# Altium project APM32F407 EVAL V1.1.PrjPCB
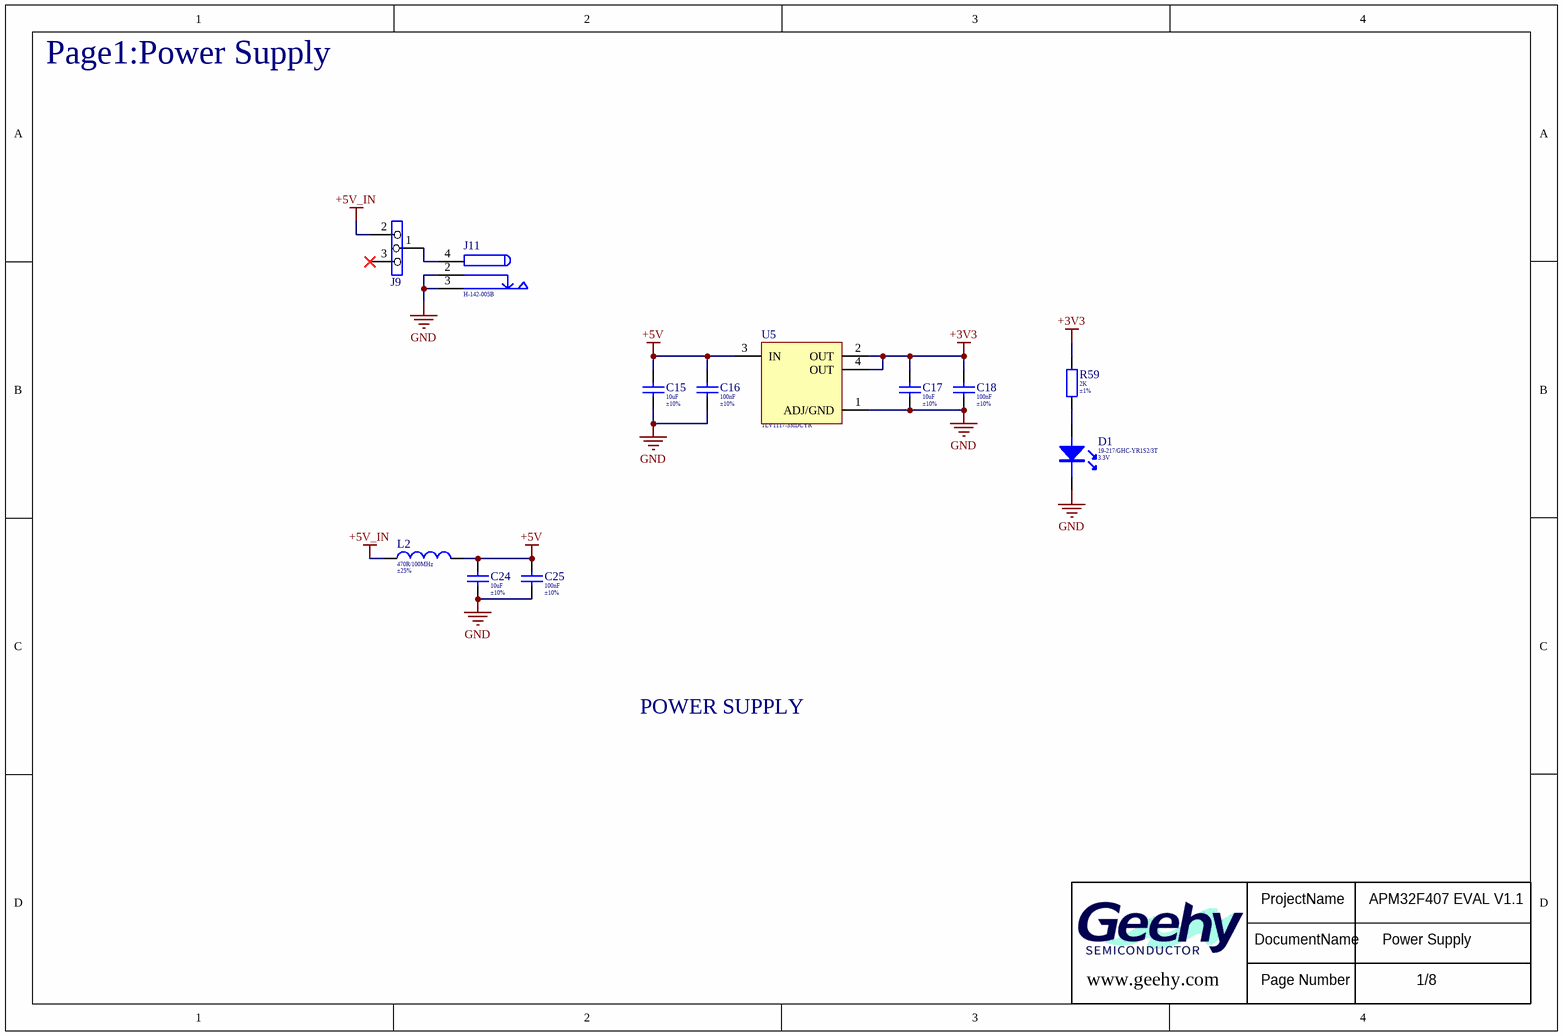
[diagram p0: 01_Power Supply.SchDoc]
8 sheets, 143 parts. Net scope: global (net labels, ports and power ports of the same name join across sheets).
Board file: APM32F407 EVAL V1.1.PcbDoc
Sheets:
  01_Power Supply.SchDoc
  02_MCU_Connect.SchDoc
  03_GPIO.SchDoc
  04_ETH.SchDoc
  05_Memory&Camera&Button&BUZ.SchDoc
  06_TFCard&LED&LCD.SchDoc
  07_Communication.SchDoc
  08_USB&JTAG.SchDoc

## Sheet 01_Power Supply.SchDoc
size A4; CompanyName: CYGRD; Organization: Altium Limited; Address1: L3, 12a Rodborough Rd; Address2: Frenchs Forest; Address3: NSW; Address4: Australia 2086

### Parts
C15  Tolerance: ±10%  [C0805]  (hidden comment: 10uF)
C16  Tolerance: ±10%  [C0603]  (hidden comment: 100nF)
C17  Tolerance: ±10%  [C0805]  (hidden comment: 10uF)
C18  Tolerance: ±10%  [C0603]  (hidden comment: 100nF)
C24  Tolerance: ±10%  [C0805]  (hidden comment: 10uF)
C25  Tolerance: ±10%  [C0603]  (hidden comment: 100nF)
D1  Rated Voltage: 3.3V  [LED-0603]  (hidden comment: 19-217/GHC-YR1S2/3T)
J9  KEY  (value not drawn)
J11  H-142-005B  [DC-PORT-6R3-TH-W-234]
L2  Tolerance: ±25%  [L0603]  (hidden comment: 470R/100MHz)
R59  Tolerance: ±1%  [R0603]  (hidden comment: 2K)
U5  TLV1117-33IDCYR  [SOT223-4]

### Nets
+3V3: C17.1 C18.1 R59.1 U5.2(OUT) U5.4(OUT)
+5V: C15.1 C16.1 C24.1 C25.1 L2.2 U5.3(IN)
+5V_IN: J9.2 L2.1
GND: C15.2 C16.2 C17.2 C18.2 C24.2 C25.2 D1.2 J11.2(G) J11.3(G) U5.1(ADJ/GND)
NetD1_1: D1.1 R59.2
NetJ9_1: J9.1 J11.4(P)

Not connected (* = marked no-connect by the designer): J9 3*

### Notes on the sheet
- Page1:Power Supply
- POWER SUPPLY
- ProjectName
- APM32F407 EVAL V1.1
- www.geehy.com
- DocumentName
- Page Number
- Power Supply
- 1/8

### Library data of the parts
C15 C17 C24 = CAP-2-NP-P_1: SMD,电容量10uF,额定电压50V,偏差±10%,材质X5R,0805; Allow Altenative Part: Y; Part Number: 101CC-00033IA.01; Rated Voltage: 50V; Temperature Coefficient: X5R; serial number: 25; Categories: 电容; COMPONENTLINK 1 DESCRIPTION: OpenDatasheet; Modify time: 2018年5月26号; Preferred: P
C16 C18 C25 = CAP-2-NP-P: 安装方式SMD,电容量100nF,额定电压50V,偏差±10%,材质X7R,0603; Allow Altenative Part: Y; Rated Voltage: 50V; Temperature Coefficient: X7R; serial number: 128; Categories: 电容; COMPONENTLINK 1 DESCRIPTION: OpenDatasheet; Modify time: 2018年10月27号; Preferred: P
D1 = Diode-LED-2-N2-P: SMD,封装/间距0603,额定电压3.3V,亮度普亮,绿色; Part Number: 101DL-00047CH.01; Allow Altenative Part: Y; serial number: 28; Categories: 二极管; COMPONENTLINK 1 DESCRIPTION: GetDatasheet; Modify time: 2015年11月11号; Approved: YES; Preferred: P
J11 = Socket-DCIN-3-P4G23-P: 安装方式DIP,插座,封装尺寸2.0x6.3mm,触点材质/颜色镀锡/黑色,90度,3PIN; Part Number: 102OL-00001CV.01; Allow Altenative Part: Y; serial number: 51; COMPONENTLINK 1 DESCRIPTION: OpenDatasheet; Modify time: 2016年2月17号; Approved: YES; Preferred: P
L2 = Inductor-2-NP-P: SMD,电感值无,额定电流1A,屏蔽式,0603,阻值/频率470R/100MHz; Part Number: 101LF-00024OD.01; Allow Altenative Part: Y; Rated Current: 1A; serial number: 4; Categories: 电感; COMPONENTLINK 1 DESCRIPTION: OpenDatasheet; Modify time: 2015年08月04号; Approved: YES; Preferred: P
R59 = RES-2-NP-P: Allow Altenative Part: Y; Rated Power: 1/10W; serial number: 214; Categories: 电阻; COMPONENTLINK 1 DESCRIPTION: OpenDatasheet; Modify time: 2018年10月29号; Preferred: P
U5 = PW_4_24O-P: 安装方式SMD,SOT-223-4,4PIN,线性稳压器(输入电压 4.75V~10V,输出电压3.3V,输出电流800mA); Allow Altenative Part: Y; serial number: 334; Categories: IC; COMPONENTLINK 1 DESCRIPTION: OpenDatasheet; Modify time: 2017年01月07号; Approved: YES; Preferred: P

## Sheet 02_MCU_Connect.SchDoc
size A4; CompanyName: CYGRD; Organization: Altium Limited; Address1: L3, 12a Rodborough Rd; Address2: Frenchs Forest; Address3: NSW; Address4: Australia 2086
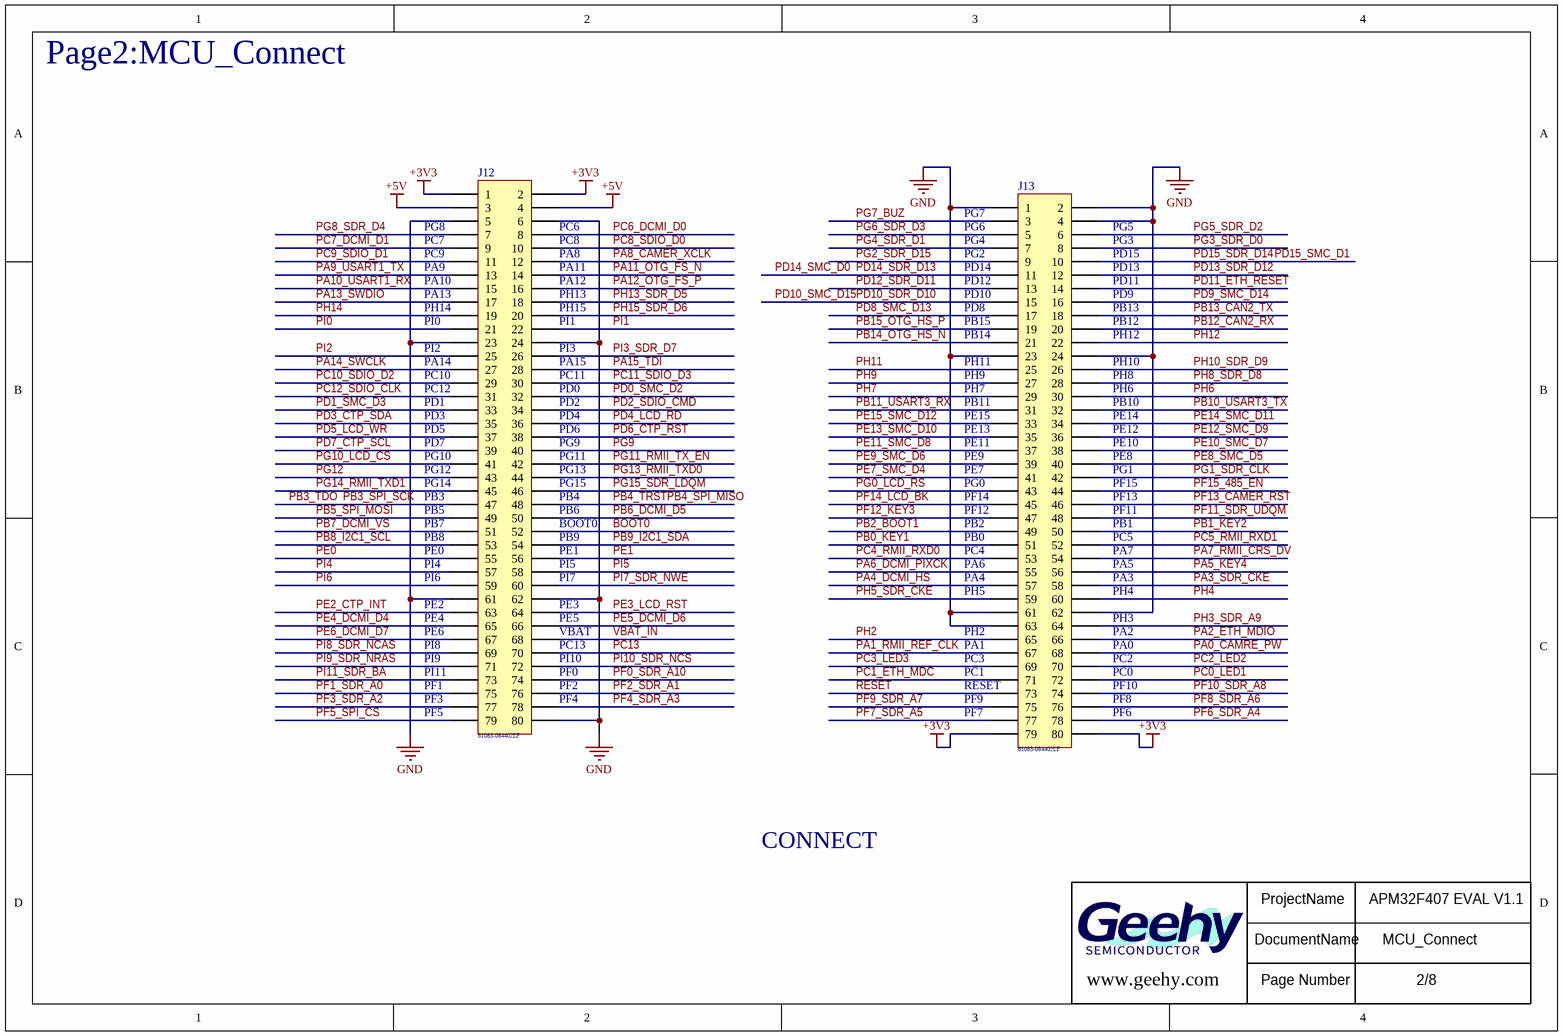
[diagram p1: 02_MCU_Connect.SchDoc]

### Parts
J12  61083-084402LF  [B2B2X40P-0R8-SM-Z-H7R7]
J13  61083-084402LF  [B2B2X40P-0R8-SM-Z-H7R7]

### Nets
+3V3: J12.1 J12.2 J13.79 J13.80
+5V: J12.3 J12.4
GND: J12.5 J12.6 J12.23 J12.24 J12.61 J12.62 J12.80 J13.1 J13.2 J13.4 J13.23 J13.24 J13.61 J13.62 J13.63
BOOT0: J12.52
PA0_CAMRE_PW: J13.68
PA1_RMII_REF_CLK: J13.67
PA2_ETH_MDIO: J13.66
PA3_SDR_CKE: J13.58
PA4_DCMI_HS: J13.57
PA5_KEY4: J13.56
PA6_DCMI_PIXCK: J13.55
PA7_RMII_CRS_DV: J13.54
PA8_CAMER_XCLK: J12.12
PA9_USART1_TX: J12.13
PA10_USART1_RX: J12.15
PA11_OTG_FS_N: J12.14
PA12_OTG_FS_P: J12.16
PA13_SWDIO: J12.17
PA14_SWCLK: J12.27
PA15_TDI: J12.28
PB0_KEY1: J13.51
PB1_KEY2: J13.50
PB2_BOOT1: J13.49
PB3_SPI_SCK: J12.47  [also labelled PB3_TDO]
PB4_SPI_MISO: J12.48  [also labelled PB4_TRST]
PB5_SPI_MOSI: J12.49
PB6_DCMI_D5: J12.50
PB7_DCMI_VS: J12.51
PB8_I2C1_SCL: J12.53
PB9_I2C1_SDA: J12.54
PB10_USART3_TX: J13.32
PB11_USART3_RX: J13.31
PB12_CAN2_RX: J13.20
PB13_CAN2_TX: J13.18
PB14_OTG_HS_N: J13.21
PB15_OTG_HS_P: J13.19
PC0_LED1: J13.72
PC1_ETH_MDC: J13.71
PC2_LED2: J13.70
PC3_LED3: J13.69
PC4_RMII_RXD0: J13.53
PC5_RMII_RXD1: J13.52
PC6_DCMI_D0: J12.8
PC7_DCMI_D1: J12.9
PC8_SDIO_D0: J12.10
PC9_SDIO_D1: J12.11
PC10_SDIO_D2: J12.29
PC11_SDIO_D3: J12.30
PC12_SDIO_CLK: J12.31
PC13: J12.70
PD0_SMC_D2: J12.32
PD1_SMC_D3: J12.33
PD2_SDIO_CMD: J12.34
PD3_CTP_SDA: J12.35
PD4_LCD_RD: J12.36
PD5_LCD_WR: J12.37
PD6_CTP_RST: J12.38
PD7_CTP_SCL: J12.39
PD8_SMC_D13: J13.17
PD9_SMC_D14: J13.16
PD10_SDR_D10: J13.15  [also labelled PD10_SMC_D15]
PD11_ETH_RESET: J13.14
PD12_SDR_D11: J13.13
PD13_SDR_D12: J13.12
PD14_SDR_D13: J13.11  [also labelled PD14_SMC_D0]
PD15_SDR_D14: J13.10  [also labelled PD15_SMC_D1]
PE0: J12.55
PE1: J12.56
PE2_CTP_INT: J12.63
PE3_LCD_RST: J12.64
PE4_DCMI_D4: J12.65
PE5_DCMI_D6: J12.66
PE6_DCMI_D7: J12.67
PE7_SMC_D4: J13.41
PE8_SMC_D5: J13.40
PE9_SMC_D6: J13.39
PE10_SMC_D7: J13.38
PE11_SMC_D8: J13.37
PE12_SMC_D9: J13.36
PE13_SMC_D10: J13.35
PE14_SMC_D11: J13.34
PE15_SMC_D12: J13.33
PF0_SDR_A10: J12.74
PF1_SDR_A0: J12.75
PF2_SDR_A1: J12.76
PF3_SDR_A2: J12.77
PF4_SDR_A3: J12.78
PF5_SPI_CS: J12.79
PF6_SDR_A4: J13.78
PF7_SDR_A5: J13.77
PF8_SDR_A6: J13.76
PF9_SDR_A7: J13.75
PF10_SDR_A8: J13.74
PF11_SDR_UDQM: J13.48
PF12_KEY3: J13.47
PF13_CAMER_RST: J13.46
PF14_LCD_BK: J13.45
PF15_485_EN: J13.44
PG0_LCD_RS: J13.43
PG1_SDR_CLK: J13.42
PG2_SDR_D15: J13.9
PG3_SDR_D0: J13.8
PG4_SDR_D1: J13.7
PG5_SDR_D2: J13.6
PG6_SDR_D3: J13.5
PG7_BUZ: J13.3
PG8_SDR_D4: J12.7
PG9: J12.40
PG10_LCD_CS: J12.41
PG11_RMII_TX_EN: J12.42
PG12: J12.43
PG13_RMII_TXD0: J12.44
PG14_RMII_TXD1: J12.45
PG15_SDR_LDQM: J12.46
PH2: J13.65
PH3_SDR_A9: J13.64
PH4: J13.60
PH5_SDR_CKE: J13.59
PH6: J13.30
PH7: J13.29
PH8_SDR_D8: J13.28
PH9: J13.27
PH10_SDR_D9: J13.26
PH11: J13.25
PH12: J13.22
PH13_SDR_D5: J12.18
PH14: J12.19
PH15_SDR_D6: J12.20
PI0: J12.21
PI1: J12.22
PI2: J12.25
PI3_SDR_D7: J12.26
PI4: J12.57
PI5: J12.58
PI6: J12.59
PI7_SDR_NWE: J12.60
PI8_SDR_NCAS: J12.69
PI9_SDR_NRAS: J12.71
PI10_SDR_NCS: J12.72
PI11_SDR_BA: J12.73
RESET: J13.73
VBAT_IN: J12.68

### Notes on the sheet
- Page2:MCU_Connect
- (near J12) PC7
- (near J12) PG8
- (near J12) PC8
- (near J12) PC6
- (near J13) PG7
- (near J13) PG4
- (near J13) PG6
- (near J13) PG3
- (near J13) PG5
- (near J12) PH14
- (near J12) PA13
- (near J12) PA10
- (near J12) PA9
- (near J12) PC9
- (near J12) PH15
- (near J12) PH13
- (near J12) PA12
- (near J12) PA11
- (near J12) PA8
- (near J13) PD8
- (near J13) PD10
- (near J13) PD12
- (near J13) PD14
- (near J13) PG2
- (near J13) PB13
- (near J13) PD9
- (near J13) PD11
- (near J13) PD13
- (near J13) PD15
- (near J12) PC10
- (near J12) PA14
- (near J12) PI2
- (near J12) PI0
- (near J12) PC11
- (near J12) PA15
- (near J12) PI3
- (near J12) PI1
- (near J13) PH9
- (near J13) PH11
- (near J13) PB14
- (near J13) PB15
- (near J13) PH8
- (near J13) PH10
- (near J13) PH12
- (near J13) PB12
- (near J12) PD7
- (near J12) PD5
- (near J12) PD3
- (near J12) PD1
- (near J12) PC12
- (near J12) PG9
- (near J12) PD6
- (near J12) PD4
- (near J12) PD2
- (near J12) PD0
- (near J13) PE11
- (near J13) PE13
- (near J13) PE15
- (near J13) PB11
- (near J13) PH7
- (near J13) PE10
- (near J13) PE12
- (near J13) PE14
- (near J13) PB10
- (near J13) PH6
- (near J12) PB5
- (near J12) PB3
- (near J12) PG14
- (near J12) PG12
- (near J12) PG10
- (near J12) PB6
- (near J12) PB4
- (near J12) PG15
- (near J12) PG13
- (near J12) PG11
- (near J13) PF12
- (near J13) PF14
- (near J13) PG0
- (near J13) PE7
- (near J13) PE9
- (near J13) PF11
- (near J13) PF13
- (near J13) PF15
- (near J13) PG1
- (near J13) PE8
- (near J12) PI6
- (near J12) PI4
- (near J12) PE0
- (near J12) PB8
- (near J12) PB7
- (near J12) PI7
- (near J12) PI5
- (near J12) PE1
- (near J12) PB9
- (near J12) BOOT0
- (near J13) PA4
- (near J13) PA6
- (near J13) PC4
- (near J13) PB0
- (near J13) PB2
- (near J13) PA3
- (near J13) PA5
- (near J13) PA7
- (near J13) PC5
- (near J13) PB1
- (near J12) PI8
- (near J12) PE6
- (near J12) PE4
- (near J12) PE2
- (near J12) PC13
- (near J12) VBAT
- (near J12) PE5
- (near J12) PE3
- (near J13) PA1
- (near J13) PH2
- (near J13) PH5
- (near J13) PA0
- (near J13) PA2
- (near J13) PH3
- (near J13) PH4
- (near J12) PF5
- (near J12) PF3
- (near J12) PF1
- (near J12) PI11
- (near J12) PI9
- (near J12) PF4
- (near J12) PF2
- (near J12) PF0
- (near J12) PI10
- (near J13) PF7
- (near J13) PF9
- (near J13) RESET
- (near J13) PC1
- (near J13) PC3
- (near J13) PF6
- (near J13) PF8
- (near J13) PF10
- (near J13) PC0
- (near J13) PC2
- CONNECT
- ProjectName
- APM32F407 EVAL V1.1
- www.geehy.com
- DocumentName
- Page Number
- MCU_Connect
- 2/8

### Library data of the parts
J12 J13 = 101NH-00011CO.01: SMD,插头,封装脚距0.80mm,180度,引脚数目2x40PIN,塑高/针长7.7mm/无,白色; Allow Altenative Part: Y; serial number: 305; Categories: 连接器; COMPONENTLINK 1 DESCRIPTION: GetDatasheet; Modify time: 2017年09月11号; Approved: YES

## Sheet 03_GPIO.SchDoc
size A4; CompanyName: CYGRD; Organization: Altium Limited; Address1: L3, 12a Rodborough Rd; Address2: Frenchs Forest; Address3: NSW; Address4: Australia 2086
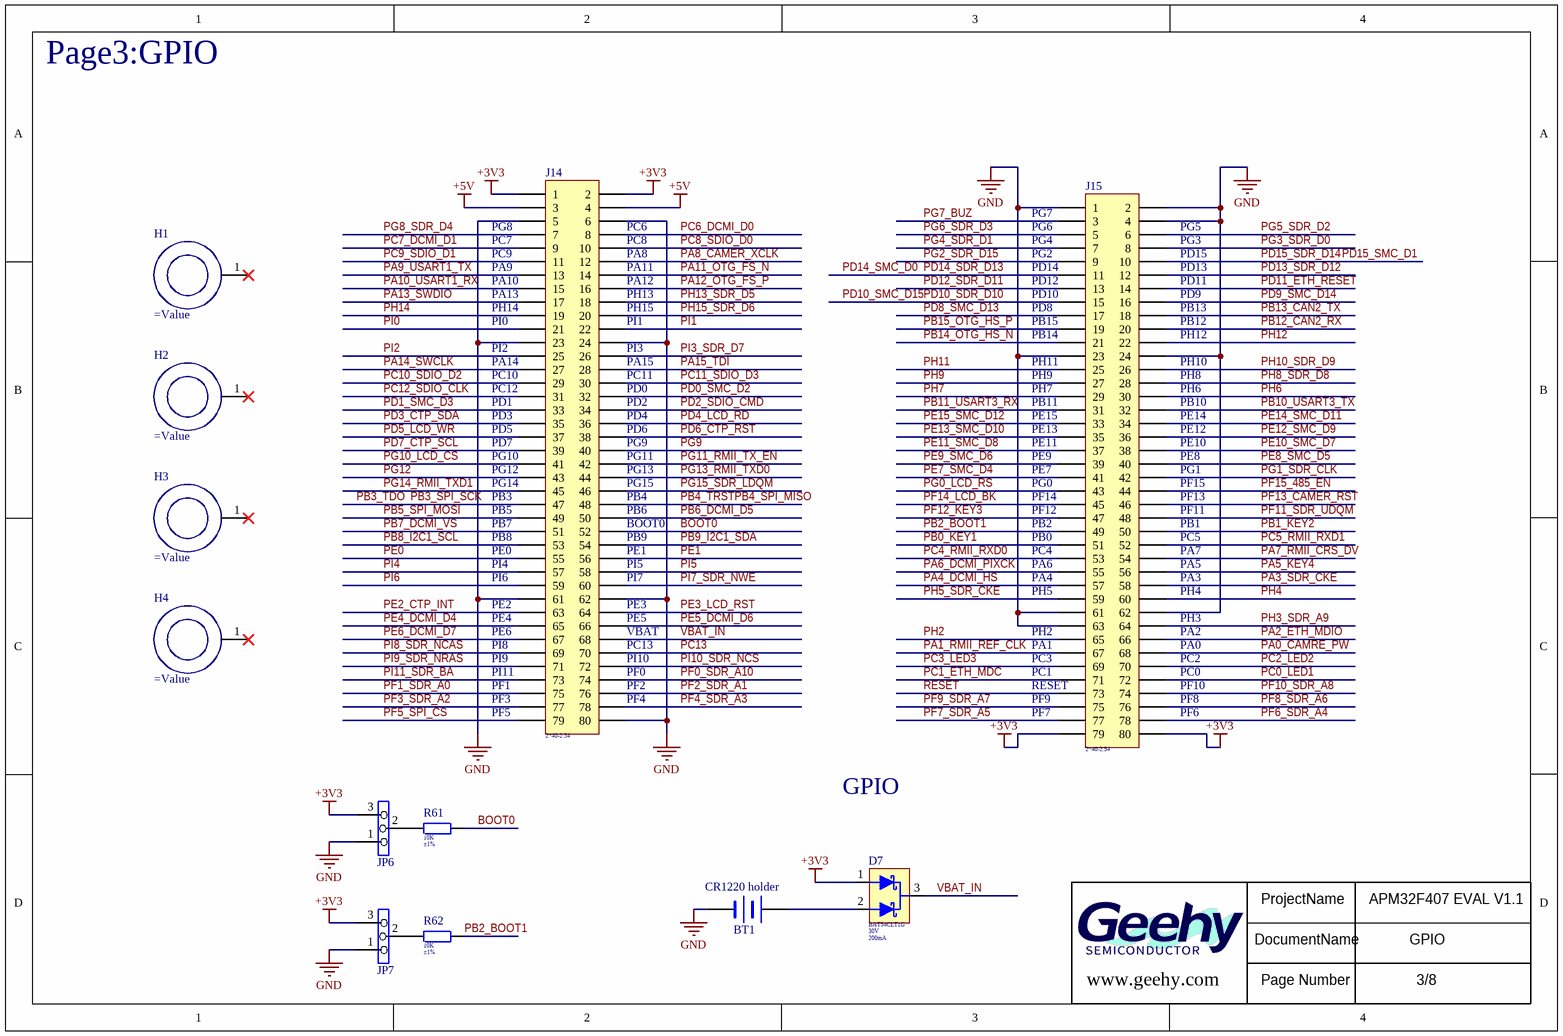
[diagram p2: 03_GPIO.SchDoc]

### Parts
BT1  CR1220 holder  [LI1220_1]
D7  Rated Voltage: 30V  Rated Current: 200mA  [SOT-23]  (hidden comment: BAT54CLT1G)
H1  (no value)  [THC5R5D3R4-M3-PTH]
H2  (no value)  [THC5R5D3R4-M3-PTH]
H3  (no value)  [THC5R5D3R4-M3-PTH]
H4  (no value)  [THC5R5D3R4-M3-PTH]
J14  2*40-2.54  [2*40-2.54]
J15  2*40-2.54  [2*40-2.54]
JP6  (no value)  [SIP3]
JP7  (no value)  [SIP3]
R61  Tolerance: ±1%  [R0603]  (hidden comment: 10K)
R62  Tolerance: ±1%  [R0603]  (hidden comment: 10K)

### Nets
+3V3: D7.1(A1) J14.1 J14.2 J15.79 J15.80 JP6.3 JP7.3
+5V: J14.3 J14.4
GND: BT1.2(-) J14.5 J14.6 J14.23 J14.24 J14.61 J14.62 J14.80 J15.1 J15.2 J15.4 J15.23 J15.24 J15.61 J15.62 J15.63 JP6.1 JP7.1
BOOT0: J14.52 R61.2
PA0_CAMRE_PW: J15.68
PA1_RMII_REF_CLK: J15.67
PA2_ETH_MDIO: J15.66
PA3_SDR_CKE: J15.58
PA4_DCMI_HS: J15.57
PA5_KEY4: J15.56
PA6_DCMI_PIXCK: J15.55
PA7_RMII_CRS_DV: J15.54
PA8_CAMER_XCLK: J14.12
PA9_USART1_TX: J14.13
PA10_USART1_RX: J14.15
PA11_OTG_FS_N: J14.14
PA12_OTG_FS_P: J14.16
PA13_SWDIO: J14.17
PA14_SWCLK: J14.27
PA15_TDI: J14.28
PB0_KEY1: J15.51
PB1_KEY2: J15.50
PB2_BOOT1: J15.49 R62.2
PB3_SPI_SCK: J14.47  [also labelled PB3_TDO]
PB4_SPI_MISO: J14.48  [also labelled PB4_TRST]
PB5_SPI_MOSI: J14.49
PB6_DCMI_D5: J14.50
PB7_DCMI_VS: J14.51
PB8_I2C1_SCL: J14.53
PB9_I2C1_SDA: J14.54
PB10_USART3_TX: J15.32
PB11_USART3_RX: J15.31
PB12_CAN2_RX: J15.20
PB13_CAN2_TX: J15.18
PB14_OTG_HS_N: J15.21
PB15_OTG_HS_P: J15.19
PC0_LED1: J15.72
PC1_ETH_MDC: J15.71
PC2_LED2: J15.70
PC3_LED3: J15.69
PC4_RMII_RXD0: J15.53
PC5_RMII_RXD1: J15.52
PC6_DCMI_D0: J14.8
PC7_DCMI_D1: J14.9
PC8_SDIO_D0: J14.10
PC9_SDIO_D1: J14.11
PC10_SDIO_D2: J14.29
PC11_SDIO_D3: J14.30
PC12_SDIO_CLK: J14.31
PC13: J14.70
PD0_SMC_D2: J14.32
PD1_SMC_D3: J14.33
PD2_SDIO_CMD: J14.34
PD3_CTP_SDA: J14.35
PD4_LCD_RD: J14.36
PD5_LCD_WR: J14.37
PD6_CTP_RST: J14.38
PD7_CTP_SCL: J14.39
PD8_SMC_D13: J15.17
PD9_SMC_D14: J15.16
PD10_SDR_D10: J15.15  [also labelled PD10_SMC_D15]
PD11_ETH_RESET: J15.14
PD12_SDR_D11: J15.13
PD13_SDR_D12: J15.12
PD14_SDR_D13: J15.11  [also labelled PD14_SMC_D0]
PD15_SDR_D14: J15.10  [also labelled PD15_SMC_D1]
PE0: J14.55
PE1: J14.56
PE2_CTP_INT: J14.63
PE3_LCD_RST: J14.64
PE4_DCMI_D4: J14.65
PE5_DCMI_D6: J14.66
PE6_DCMI_D7: J14.67
PE7_SMC_D4: J15.41
PE8_SMC_D5: J15.40
PE9_SMC_D6: J15.39
PE10_SMC_D7: J15.38
PE11_SMC_D8: J15.37
PE12_SMC_D9: J15.36
PE13_SMC_D10: J15.35
PE14_SMC_D11: J15.34
PE15_SMC_D12: J15.33
PF0_SDR_A10: J14.74
PF1_SDR_A0: J14.75
PF2_SDR_A1: J14.76
PF3_SDR_A2: J14.77
PF4_SDR_A3: J14.78
PF5_SPI_CS: J14.79
PF6_SDR_A4: J15.78
PF7_SDR_A5: J15.77
PF8_SDR_A6: J15.76
PF9_SDR_A7: J15.75
PF10_SDR_A8: J15.74
PF11_SDR_UDQM: J15.48
PF12_KEY3: J15.47
PF13_CAMER_RST: J15.46
PF14_LCD_BK: J15.45
PF15_485_EN: J15.44
PG0_LCD_RS: J15.43
PG1_SDR_CLK: J15.42
PG2_SDR_D15: J15.9
PG3_SDR_D0: J15.8
PG4_SDR_D1: J15.7
PG5_SDR_D2: J15.6
PG6_SDR_D3: J15.5
PG7_BUZ: J15.3
PG8_SDR_D4: J14.7
PG9: J14.40
PG10_LCD_CS: J14.41
PG11_RMII_TX_EN: J14.42
PG12: J14.43
PG13_RMII_TXD0: J14.44
PG14_RMII_TXD1: J14.45
PG15_SDR_LDQM: J14.46
PH2: J15.65
PH3_SDR_A9: J15.64
PH4: J15.60
PH5_SDR_CKE: J15.59
PH6: J15.30
PH7: J15.29
PH8_SDR_D8: J15.28
PH9: J15.27
PH10_SDR_D9: J15.26
PH11: J15.25
PH12: J15.22
PH13_SDR_D5: J14.18
PH14: J14.19
PH15_SDR_D6: J14.20
PI0: J14.21
PI1: J14.22
PI2: J14.25
PI3_SDR_D7: J14.26
PI4: J14.57
PI5: J14.58
PI6: J14.59
PI7_SDR_NWE: J14.60
PI8_SDR_NCAS: J14.69
PI9_SDR_NRAS: J14.71
PI10_SDR_NCS: J14.72
PI11_SDR_BA: J14.73
RESET: J15.73
VBAT_IN: D7.3(K) J14.68
NetBT1_1: BT1.1(+) D7.2(A2)
NetJP6_2: JP6.2 R61.1
NetJP7_2: JP7.2 R62.1

Not connected (* = marked no-connect by the designer): H1 1*; H2 1*; H3 1*; H4 1*

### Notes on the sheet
- Page3:GPIO
- (near J14) PC7
- (near J14) PG8
- (near J14) PC8
- (near J14) PC6
- (near J15) PG7
- (near J15) PG4
- (near J15) PG6
- (near J15) PG3
- (near J15) PG5
- (near J14) PH14
- (near J14) PA13
- (near J14) PA10
- (near J14) PA9
- (near J14) PC9
- (near J14) PH15
- (near J14) PH13
- (near J14) PA12
- (near J14) PA11
- (near J14) PA8
- (near J15) PD8
- (near J15) PD10
- (near J15) PD12
- (near J15) PD14
- (near J15) PG2
- (near J15) PB13
- (near J15) PD9
- (near J15) PD11
- (near J15) PD13
- (near J15) PD15
- (near J14) PC10
- (near J14) PA14
- (near J14) PI2
- (near J14) PI0
- (near J14) PC11
- (near J14) PA15
- (near J14) PI3
- (near J14) PI1
- (near J15) PH9
- (near J15) PH11
- (near J15) PB14
- (near J15) PB15
- (near J15) PH8
- (near J15) PH10
- (near J15) PH12
- (near J15) PB12
- (near J14) PD7
- (near J14) PD5
- (near J14) PD3
- (near J14) PD1
- (near J14) PC12
- (near J14) PG9
- (near J14) PD6
- (near J14) PD4
- (near J14) PD2
- (near J14) PD0
- (near J15) PE11
- (near J15) PE13
- (near J15) PE15
- (near J15) PB11
- (near J15) PH7
- (near J15) PE10
- (near J15) PE12
- (near J15) PE14
- (near J15) PB10
- (near J15) PH6
- (near J14) PB5
- (near J14) PB3
- (near J14) PG14
- (near J14) PG12
- (near J14) PG10
- (near J14) PB6
- (near J14) PB4
- (near J14) PG15
- (near J14) PG13
- (near J14) PG11
- (near J15) PF12
- (near J15) PF14
- (near J15) PG0
- (near J15) PE7
- (near J15) PE9
- (near J15) PF11
- (near J15) PF13
- (near J15) PF15
- (near J15) PG1
- (near J15) PE8
- (near J14) PI6
- (near J14) PI4
- (near J14) PE0
- (near J14) PB8
- (near J14) PB7
- (near J14) PI7
- (near J14) PI5
- (near J14) PE1
- (near J14) PB9
- (near J14) BOOT0
- (near J15) PA4
- (near J15) PA6
- (near J15) PC4
- (near J15) PB0
- (near J15) PB2
- (near J15) PA3
- (near J15) PA5
- (near J15) PA7
- (near J15) PC5
- (near J15) PB1
- (near J14) PI8
- (near J14) PE6
- (near J14) PE4
- (near J14) PE2
- (near J14) PC13
- (near J14) VBAT
- (near J14) PE5
- (near J14) PE3
- (near J15) PA1
- (near J15) PH2
- (near J15) PH5
- (near J15) PA0
- (near J15) PA2
- (near J15) PH3
- (near J15) PH4
- (near J14) PF5
- (near J14) PF3
- (near J14) PF1
- (near J14) PI11
- (near J14) PI9
- (near J14) PF4
- (near J14) PF2
- (near J14) PF0
- (near J14) PI10
- (near J15) PF7
- (near J15) PF9
- (near J15) RESET
- (near J15) PC1
- (near J15) PC3
- (near J15) PF6
- (near J15) PF8
- (near J15) PF10
- (near J15) PC0
- (near J15) PC2
- GPIO
- ProjectName
- APM32F407 EVAL V1.1
- www.geehy.com
- DocumentName
- Page Number
- 3/8

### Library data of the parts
BT1 = BATTERY
D7 = 101DS-00053BA.01: 安装方式SMD,SOT-23,额定电压30V,电流200mA; Allow Altenative Part: Y; serial number: 216; Categories: 二极管; COMPONENTLINK 1 DESCRIPTION: GetDatasheet; Modify time: 2019年9月21号
H1-H4 = M3-PTH: Part Number: M3-PTH; Allow Altenative Part: Y; serial number: 15; Categories: 符号; Modify time: 2017年2月13日; Approved: YES
J14 J15 = 101NH-00011CO.01: Allow Altenative Part: Y; serial number: 305; COMPONENTLINK 1 DESCRIPTION: GetDatasheet; Modify time: 2017年09月11号; Approved: YES
JP6 JP7 = Jumper3
R61 R62 = RES-2-NP-P: as R59 on sheet 01_Power Supply

## Sheet 04_ETH.SchDoc
size A4; CompanyName: CYGRD; Organization: Altium Limited; Address1: L3, 12a Rodborough Rd; Address2: Frenchs Forest; Address3: NSW; Address4: Australia 2086
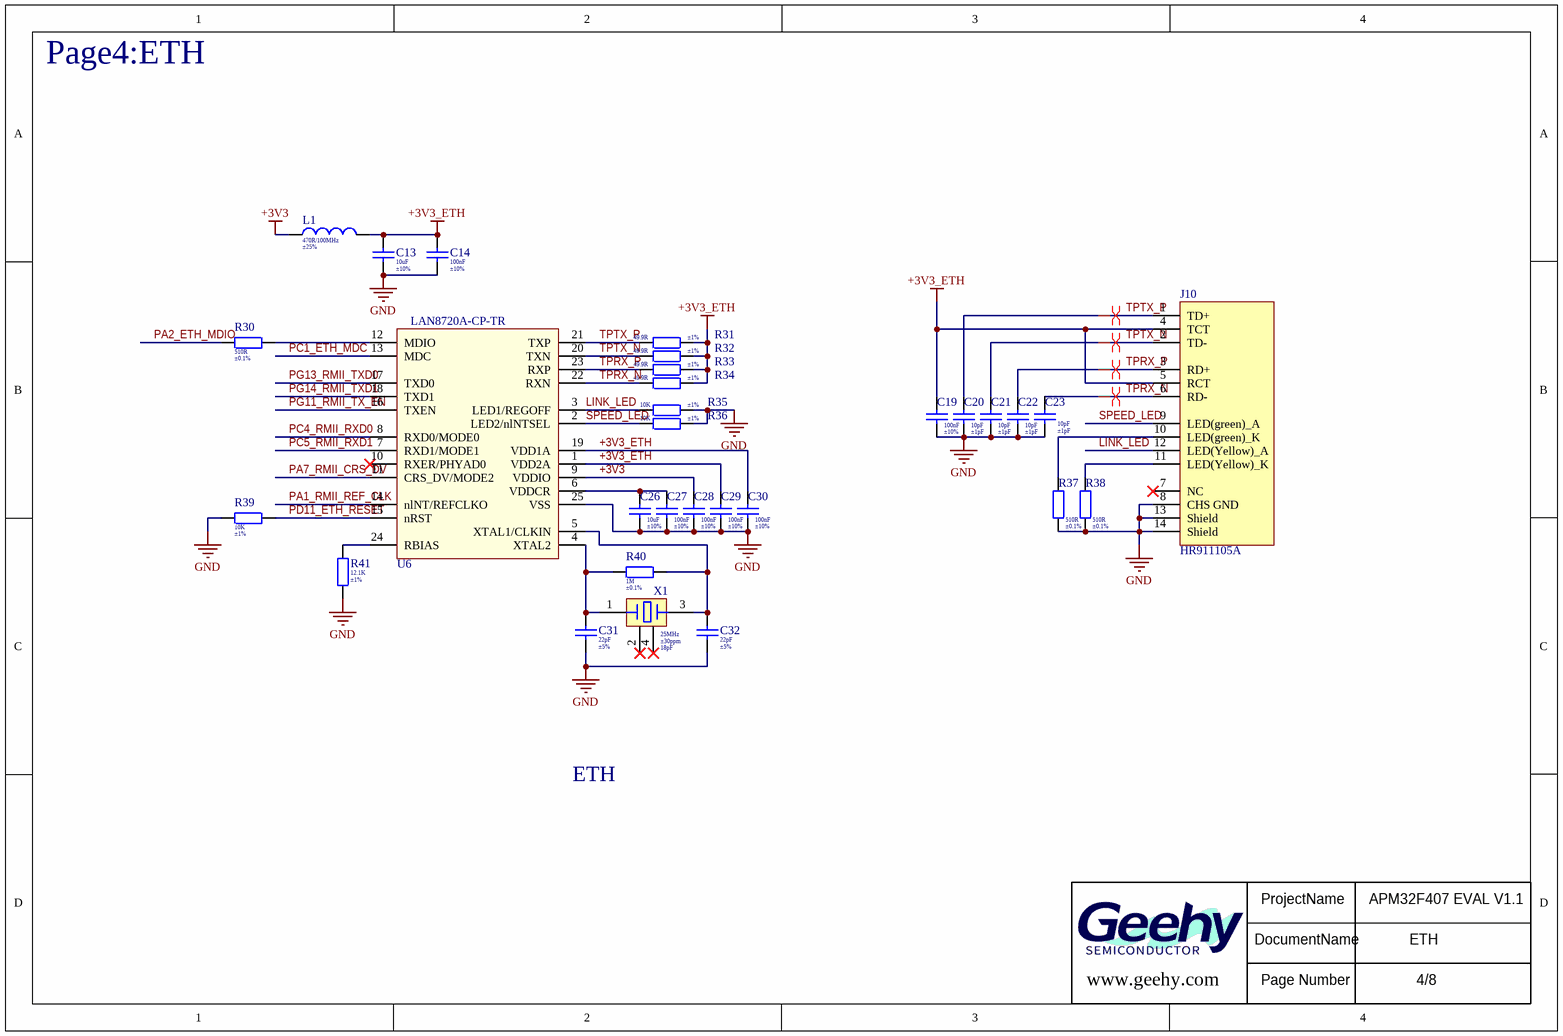
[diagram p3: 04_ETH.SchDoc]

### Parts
C13  Tolerance: ±10%  [C0805]  (hidden comment: 10uF)
C14  Tolerance: ±10%  [C0603]  (hidden comment: 100nF)
C19  Tolerance: ±10%  [C0603]  (hidden comment: 100nF)
C20  Tolerance: ±1pF  [C0603]  (hidden comment: 10pF)
C21  Tolerance: ±1pF  [C0603]  (hidden comment: 10pF)
C22  Tolerance: ±1pF  [C0603]  (hidden comment: 10pF)
C23  Tolerance: ±1pF  [C0603]  (hidden comment: 10pF)
C26  Tolerance: ±10%  [C0805]  (hidden comment: 10uF)
C27  Tolerance: ±10%  [C0603]  (hidden comment: 100nF)
C28  Tolerance: ±10%  [C0603]  (hidden comment: 100nF)
C29  Tolerance: ±10%  [C0603]  (hidden comment: 100nF)
C30  Tolerance: ±10%  [C0603]  (hidden comment: 100nF)
C31  Tolerance: ±5%  [C0603]  (hidden comment: 22pF)
C32  Tolerance: ±5%  [C0603]  (hidden comment: 22pF)
J10  HR911105A  [RJ45-21R3X16R1X13R4-TH-W]
L1  Tolerance: ±25%  [L0603]  (hidden comment: 470R/100MHz)
R30  Tolerance: ±0.1%  [R0603]  (hidden comment: 510R)
R31  Tolerance: ±1%  [R0603]  (hidden comment: 49.9R)
R32  Tolerance: ±1%  [R0603]  (hidden comment: 49.9R)
R33  Tolerance: ±1%  [R0603]  (hidden comment: 49.9R)
R34  Tolerance: ±1%  [R0603]  (hidden comment: 49.9R)
R35  Tolerance: ±1%  [R0603]  (hidden comment: 10K)
R36  Tolerance: ±1%  [R0603]  (hidden comment: 10K)
R37  Tolerance: ±0.1%  [R0603]  (hidden comment: 510R)
R38  Tolerance: ±0.1%  [R0603]  (hidden comment: 510R)
R39  Tolerance: ±1%  [R0603]  (hidden comment: 10K)
R40  Tolerance: ±0.1%  [R0603]  (hidden comment: 1M)
R41  Tolerance: ±1%  [R0603]  (hidden comment: 12.1K)
U6  LAN8720A-CP-TR  [QFN24-0R5-4X4-T]
X1  Tolerance: ±30ppm  Other: 18pF  [XTAL3225]  (hidden comment: 25MHz)

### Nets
+3V3: C28.1 L1.1 U6.9(VDDIO)
+3V3_ETH: C13.1 C14.1 C19.1 C29.1 C30.1 J10.4(TCT) J10.5(RCT) L1.2 R31.1 R32.1 R33.1 R34.1 U6.1(VDD2A) U6.19(VDD1A)
GND: C13.2 C14.2 C19.2 C20.1 C21.1 C22.1 C23.1 C26.2 C27.2 C28.2 C29.2 C30.2 C31.1 C32.1 J10.8(CHS_GND) J10.13(Shield) J10.14(Shield) R35.2 R36.2 R37.2 R38.2 R39.1 R41.2 U6.25(VSS)
LINK_LED: J10.12(LED(Yellow)_A) R35.1 U6.3(LED1/REGOFF)
PA1_RMII_REF_CLK: U6.14(nlNT/REFCLKO)
PA2_ETH_MDIO: R30.2
PA7_RMII_CRS_DV: U6.11(CRS_DV/MODE2)
PC1_ETH_MDC: U6.13(MDC)
PC4_RMII_RXD0: U6.8(RXD0/MODE0)
PC5_RMII_RXD1: U6.7(RXD1/MODE1)
PD11_ETH_RESET: R39.2 U6.15(nRST)
PG11_RMII_TX_EN: U6.16(TXEN)
PG13_RMII_TXD0: U6.17(TXD0)
PG14_RMII_TXD1: U6.18(TXD1)
SPEED_LED: J10.9(LED(green)_A) R36.1 U6.2(LED2/nlNTSEL)
TPRX_N: C23.2 J10.6(RD-) R34.2 U6.22(RXN)
TPRX_P: C22.2 J10.3(RD+) R33.2 U6.23(RXP)
TPTX_N: C21.2 J10.2(TD-) R32.2 U6.20(TXN)
TPTX_P: C20.2 J10.1(TD+) R31.2 U6.21(TXP)
NetC26_1: C26.1 C27.1 U6.6(VDDCR)
NetC31_2: C31.2 R40.2 U6.4(XTAL2) X1.1
NetC32_2: C32.2 R40.1 U6.5(XTAL1/CLKIN) X1.3
NetJ10_10: J10.10(LED(green)_K) R37.1
NetJ10_11: J10.11(LED(Yellow)_K) R38.1
NetR30_1: R30.1 U6.12(MDIO)
NetR41_1: R41.1 U6.24(RBIAS)

Not connected (* = marked no-connect by the designer): J10 7(NC)*; U6 10(RXER/PHYAD0)*; X1 2(GND)* 4(GND)*

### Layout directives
differential pair: TPRX_N, TPRX_P, TPTX_N, TPTX_P

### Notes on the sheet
- Page4:ETH
- ETH
- ProjectName
- APM32F407 EVAL V1.1
- www.geehy.com
- DocumentName
- Page Number
- 4/8

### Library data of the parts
C13 C26 = CAP-2-NP-P_1: as C15 on sheet 01_Power Supply
C14 C19 C27-C30 = CAP-2-NP-P: as C16 on sheet 01_Power Supply
C20-C23 = 101CC-00365BE.01: SMD,电容量10pF,额定电压50V,偏差±1pF,材质C0G,0603; Allow Altenative Part: Y; Rated Voltage: 50V; Temperature Coefficient: C0G; serial number: 13; Categories: 电容; COMPONENTLINK 1 DESCRIPTION: GetDatasheet; Modify time: 2015年07月10号; Approved: YES
C31 C32 = 101CC-00036IA.01: 安装方式SMD,电容量22pF,额定电压50V,偏差±5%,材质NP0,0603; Allow Altenative Part: Y; Rated Voltage: 50V; Temperature Coefficient: NP0; serial number: 336; Categories: 电容; COMPONENTLINK 1 DESCRIPTION: GetDatasheet; Modify time: 2021年3月27号
J10 = J0011D21B
L1 = Inductor-2-NP-P: as L2 on sheet 01_Power Supply
R30 R37 R38 = 101RC-02070BW.01: 安装方式SMD,阻值510R,精度±0.1%,0603,额定功率1/10W，温度系数±50PPM/℃; Allow Altenative Part: Y; Rated Power: 1/10W; serial number: 186; Categories: 电阻; COMPONENTLINK 1 DESCRIPTION: OpenDatasheet; Modify time: 2017年05月15号
R31-R36 R39 = RES-2-NP-P: as R59 on sheet 01_Power Supply
R40 = 101RC-01958BW.01: 安装方式SMD,阻值1M,精度±0.1%,0603,额定功率1/10W，温度系数±25PPM/℃; Allow Altenative Part: Y; Rated Power: 1/10W; serial number: 134; Categories: 电阻; COMPONENTLINK 1 DESCRIPTION: OpenDatasheet; Modify time: 2016年11月08号; Approved: YES
R41 = 101RC-01821BW.01: 安装方式SMD,阻值12.1K,精度±1%,0603,额定功率1/10W; Allow Altenative Part: Y; Rated Power: 1/10W; serial number: 72; Categories: 电阻; COMPONENTLINK 1 DESCRIPTION: OpenDatasheet; Modify time: 2016年03月27号; Approved: YES
U6 = 101IK-00033AS.01: 安装方式SMD,QFN-24,24PIN,功能描述以太网PHY层芯片可通过RMII与带MAC功能的MCU通信(工作电压:1.6V~3.6V); Allow Altenative Part: Y; Categories: IC; Modify time: 2016年12月11号; serial number: 1007; COMPONENTLINK 1 DESCRIPTION: OpenDatasheet
X1 = 101XB-00048BP.01: 安装方式SMD,材质金属外壳,3225,精度±30ppm,震荡频率25MHz，负载电容18pF; Allow Altenative Part: Y; serial number: 13; Categories: 晶振; COMPONENTLINK 1 DESCRIPTION: OpenDatasheet; Modify time: 2016年2月17号; Approved: YES

## Sheet 05_Memory&Camera&Button&BUZ.SchDoc
size A4; CompanyName: CYGRD; Organization: Altium Limited; Address1: L3, 12a Rodborough Rd; Address2: Frenchs Forest; Address3: NSW; Address4: Australia 2086
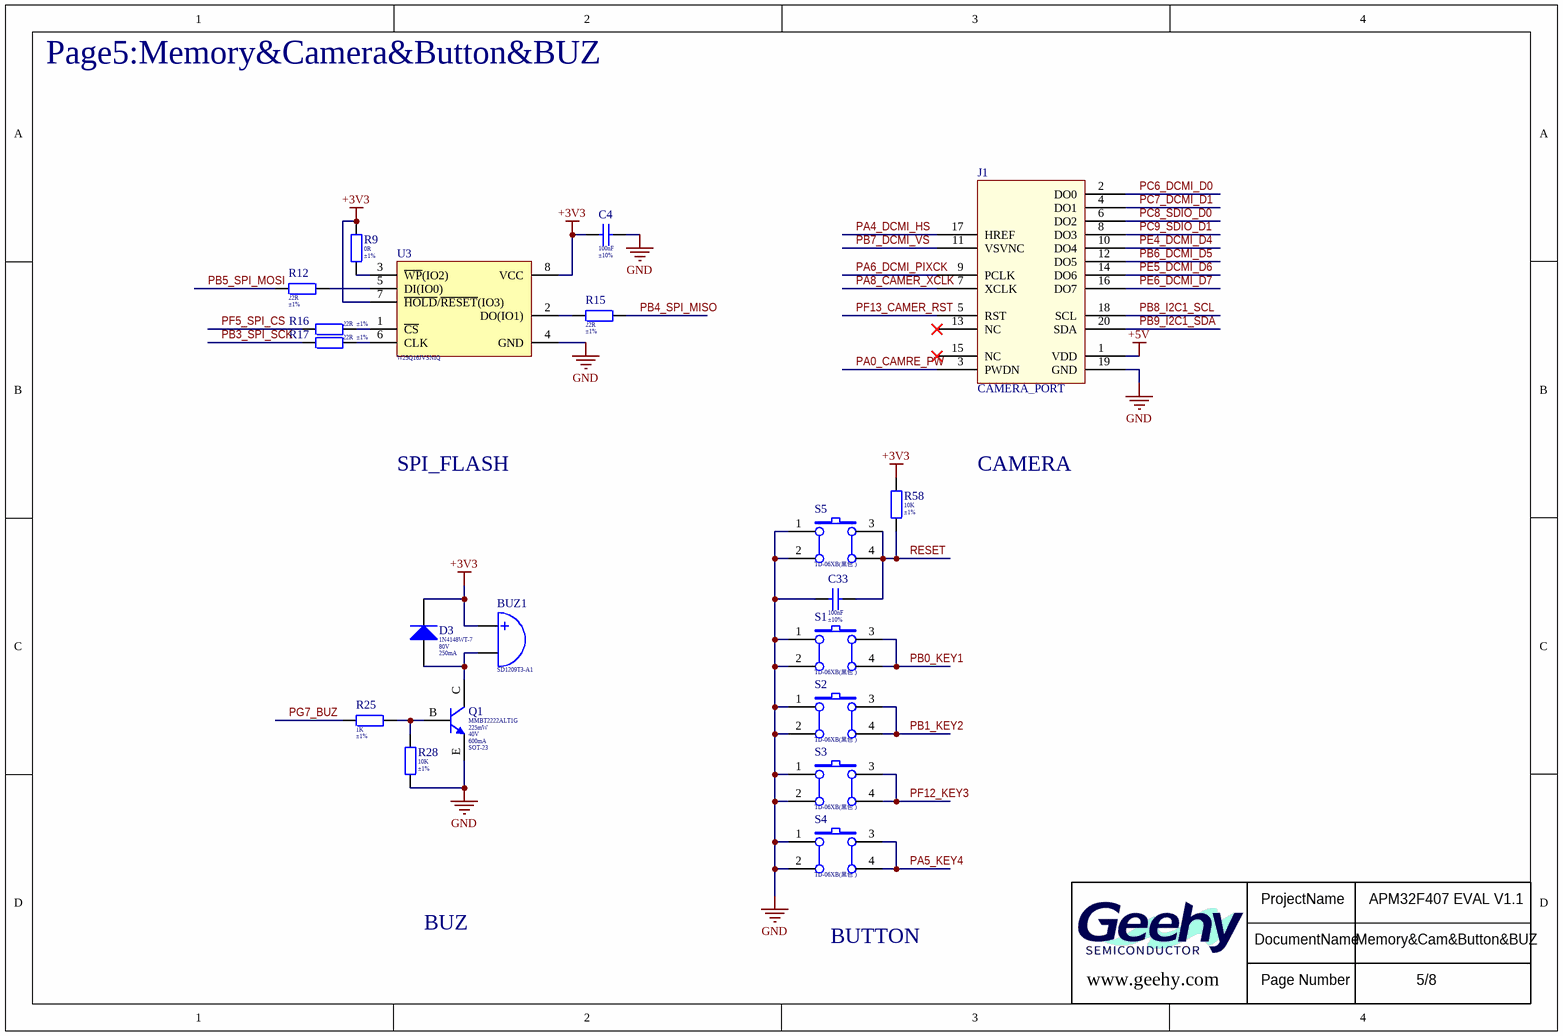
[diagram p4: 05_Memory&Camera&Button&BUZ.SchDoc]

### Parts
BUZ1  SD1209T3-A1  [BUZ5-12-0R5-9MM]
C4  Tolerance: ±10%  [C0603]  (hidden comment: 100nF)
C33  Tolerance: ±10%  [C0603]  (hidden comment: 100nF)
D3  Rated Voltage: 80V  Rated Current: 250mA  [SOD-523]  (hidden comment: 1N4148WT-7)
J1  CAMERA_PORT  [2*10-2.54]
Q1  Rated Power: 225mW  Rated Voltage: 40V  Rated Current: 600mA  Size: SOT-23  [SOT-23-BCE]  (hidden comment: MMBT2222ALT1G)
R9  Tolerance: ±1%  [R0603]  (hidden comment: 0R)
R12  Tolerance: ±1%  [R0603]  (hidden comment: 22R)
R15  Tolerance: ±1%  [R0603]  (hidden comment: 22R)
R16  Tolerance: ±1%  [R0603]  (hidden comment: 22R)
R17  Tolerance: ±1%  [R0603]  (hidden comment: 22R)
R25  Tolerance: ±1%  [R0603]  (hidden comment: 1K)
R28  Tolerance: ±1%  [R0603]  (hidden comment: 10K)
R58  Tolerance: ±1%  [R0603]  (hidden comment: 10K)
S1  TD-06XB(黑色）  [SW-SMD-6x6x7-1]
S2  TD-06XB(黑色）  [SW-SMD-6x6x7-1]
S3  TD-06XB(黑色）  [SW-SMD-6x6x7-1]
S4  TD-06XB(黑色）  [SW-SMD-6x6x7-1]
S5  TD-06XB(黑色）  [SW-SMD-6x6x7-1]
U3  W25Q16JVSNIQ  [SOIC8-1R27-5R3X5R3]

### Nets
+3V3: BUZ1.1 C4.2 D3.2 R9.2 R58.1 U3.7(~{HOLD}/~{RESET}(IO3)) U3.8(VCC)
+5V: J1.1(VDD)
GND: C4.1 C33.1 J1.19(GND) Q1.E R28.1 S1.1 S1.2 S2.1 S2.2 S3.1 S3.2 S4.1 S4.2 S5.1 S5.2 U3.4(GND)
PA0_CAMRE_PW: J1.3(PWDN)
PA4_DCMI_HS: J1.17(HREF)
PA5_KEY4: S4.3 S4.4
PA6_DCMI_PIXCK: J1.9(PCLK)
PA8_CAMER_XCLK: J1.7(XCLK)
PB0_KEY1: S1.3 S1.4
PB1_KEY2: S2.3 S2.4
PB3_SPI_SCK: R17.2
PB4_SPI_MISO: R15.1
PB5_SPI_MOSI: R12.2
PB6_DCMI_D5: J1.12(DO5)
PB7_DCMI_VS: J1.11(VSVNC)
PB8_I2C1_SCL: J1.18(SCL)
PB9_I2C1_SDA: J1.20(SDA)
PC6_DCMI_D0: J1.2(DO0)
PC7_DCMI_D1: J1.4(DO1)
PC8_SDIO_D0: J1.6(DO2)
PC9_SDIO_D1: J1.8(DO3)
PE4_DCMI_D4: J1.10(DO4)
PE5_DCMI_D6: J1.14(DO6)
PE6_DCMI_D7: J1.16(DO7)
PF5_SPI_CS: R16.2
PF12_KEY3: S3.3 S3.4
PF13_CAMER_RST: J1.5(RST)
PG7_BUZ: R25.2
RESET: C33.2 R58.2 S5.3 S5.4
NetBUZ1_2: BUZ1.2 D3.1 Q1.C
NetQ1_B: Q1.B R25.1 R28.2
NetR9_1: R9.1 U3.3(~{WP}(IO2))
NetR12_1: R12.1 U3.5(DI(IO0))
NetR15_2: R15.2 U3.2(DO(IO1))
NetR16_1: R16.1 U3.1(~{CS})
NetR17_1: R17.1 U3.6(CLK)

Not connected (* = marked no-connect by the designer): J1 13(NC)* 15(NC)*

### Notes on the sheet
- Page5:Memory&Camera&Button&BUZ
- SPI_FLASH
- CAMERA
- ProjectName
- APM32F407 EVAL V1.1
- BUZ
- BUTTON
- www.geehy.com
- DocumentName
- Page Number
- Memory&Cam&Button&BUZ
- 5/8

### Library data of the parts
BUZ1 = 102BA-00003OD.01: DIP,封装/外壳12x9mm,额定电压DC3V,频率2048Hz,黑色,间距5mm; Allow Altenative Part: Y; serial number: 1; Categories: 蜂鸣器; COMPONENTLINK 1 DESCRIPTION: GetDatasheet; Modify time: 2015年11月4号
C4 C33 = CAP-2-NP-P: as C16 on sheet 01_Power Supply
D3 = Diode-CM-2-N2-P: SMD,SOD-523（0603）,额定电压80V,电流125mA; Part Number: 101DG-00019AF.01; Allow Altenative Part: Y; serial number: 92; Categories: 二极管; COMPONENTLINK 1 DESCRIPTION: GetDatasheet; Modify time: 2015年07月28号; Approved: YES; Preferred: P
Q1 = Triode-NPN-BCE-P: SMD,封装形式SOT-23,耐压值40V,额定电流600mA,耗散功率225mW; Part Number: 101GN-00006BA.01; Allow Altenative Part: Y; serial number: 274; Categories: 三极管; COMPONENTLINK 1 DESCRIPTION: OpenDatasheet; Modify time: 2017年01月07号; Approved: YES; Preferred: P
R9 = RES-2-NP-P: SMD,阻值0R,精度±1%,0603,额定功率1/10W; Allow Altenative Part: Y; Rated Power: 1/10W; serial number: 214; Categories: 电阻; COMPONENTLINK 1 DESCRIPTION: OpenDatasheet; Modify time: 2018年10月29号; Preferred: P
R12 R15-R17 R25 R28 R58 = RES-2-NP-P: as R59 on sheet 01_Power Supply
S1-S5 = Key-LTS-4-I12O34-P: 安装方式SMD,6.0x6.0x7.0mm,4PIN,180度,黑色; Part Number: 101SA-00002FP.01; Allow Altenative Part: Y; serial number: 16; Categories: 开关; COMPONENTLINK 1 DESCRIPTION: OpenDatasheet; Modify time: 2019年5月25号; Preferred: P
U3 = 101IC-00010EA.01: SMD,SOIC-8,8PIN,功能描述16M-bit flash（电压2.7V~3.6V）; Allow Altenative Part: Y; serial number: 843; Categories: IC; COMPONENTLINK 1 DESCRIPTION: OpenDatasheet; Modify time: 2018年9月22号

## Sheet 06_TFCard&LED&LCD.SchDoc
size A4; CompanyName: CYGRD; Organization: Altium Limited; Address1: L3, 12a Rodborough Rd; Address2: Frenchs Forest; Address3: NSW; Address4: Australia 2086
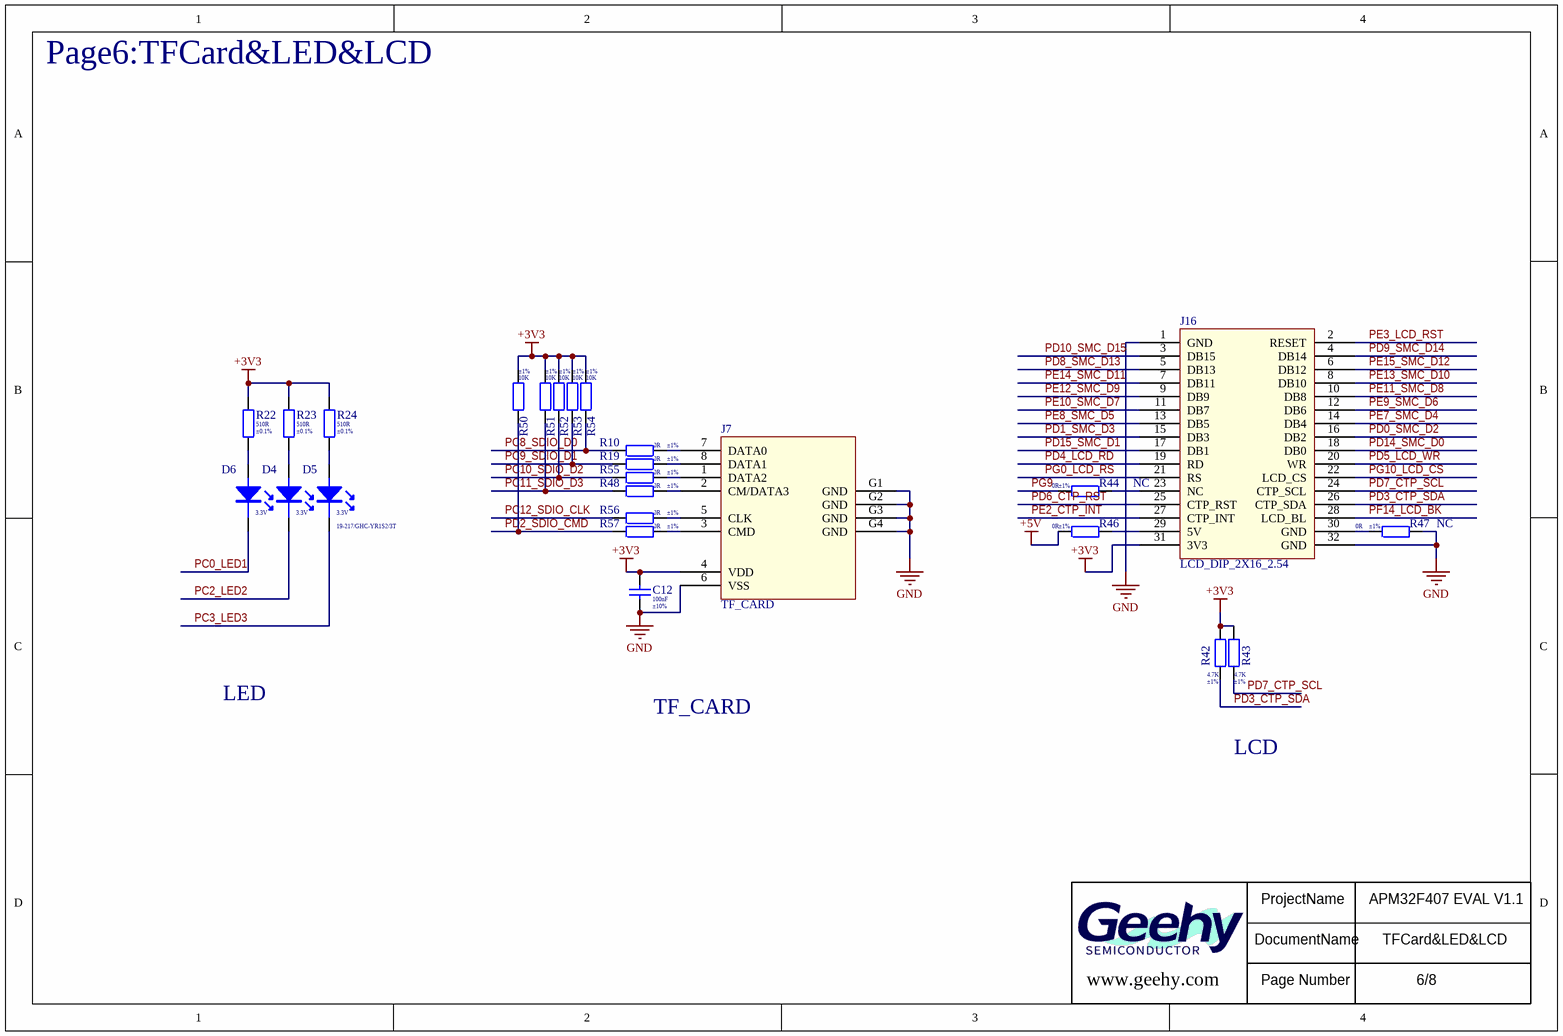
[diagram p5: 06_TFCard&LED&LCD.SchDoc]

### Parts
C12  Tolerance: ±10%  [C0603]  (hidden comment: 100nF)
D4  Rated Voltage: 3.3V  [LED-0603]  (hidden comment: 19-217/GHC-YR1S2/3T)
D5  Rated Voltage: 3.3V  [LED-0603]  (hidden comment: 19-217/GHC-YR1S2/3T)
D6  Rated Voltage: 3.3V  [LED-0603]  (hidden comment: 19-217/GHC-YR1S2/3T)
J7  TF_CARD  [SD-8]
J16  LCD_DIP_2X16_2.54  [LCD-2*16-2.54]
R10  Tolerance: ±1%  [R0603]  (hidden comment: 0R)
R19  Tolerance: ±1%  [R0603]  (hidden comment: 0R)
R22  Tolerance: ±0.1%  [R0603]  (hidden comment: 510R)
R23  Tolerance: ±0.1%  [R0603]  (hidden comment: 510R)
R24  Tolerance: ±0.1%  [R0603]  (hidden comment: 510R)
R42  Tolerance: ±1%  [R0603]  (hidden comment: 4.7K)
R43  Tolerance: ±1%  [R0603]  (hidden comment: 4.7K)
R44  NC  value 0R  Tolerance: ±1%  [R0603]
R46  Tolerance: ±1%  [R0603]  (hidden comment: 0R)
R47  NC  value 0R  Tolerance: ±1%  [R0603]
R48  Tolerance: ±1%  [R0603]  (hidden comment: 0R)
R50  Tolerance: ±1%  [R0603]  (hidden comment: 10K)
R51  Tolerance: ±1%  [R0603]  (hidden comment: 10K)
R52  Tolerance: ±1%  [R0603]  (hidden comment: 10K)
R53  Tolerance: ±1%  [R0603]  (hidden comment: 10K)
R54  Tolerance: ±1%  [R0603]  (hidden comment: 10K)
R55  Tolerance: ±1%  [R0603]  (hidden comment: 0R)
R56  Tolerance: ±1%  [R0603]  (hidden comment: 0R)
R57  Tolerance: ±1%  [R0603]  (hidden comment: 0R)

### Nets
+3V3: C12.1 J7.4(VDD) J16.31(3V3) R22.1 R23.1 R24.1 R42.2 R43.2 R50.2 R51.2 R52.2 R53.2 R54.2
+5V: R46.1
GND: C12.2 J7.6(VSS) J7.G1(GND) J7.G2(GND) J7.G3(GND) J7.G4(GND) J16.1(GND) J16.32(GND) R47.2
PC0_LED1: D6.2
PC2_LED2: D4.2
PC3_LED3: D5.2
PC8_SDIO_D0: R10.2 R54.1
PC9_SDIO_D1: R19.2 R53.1
PC10_SDIO_D2: R52.1 R55.2
PC11_SDIO_D3: R48.2 R51.1
PC12_SDIO_CLK: R56.2
PD0_SMC_D2: J16.16(DB2)
PD1_SMC_D3: J16.15(DB3)
PD2_SDIO_CMD: R50.1 R57.2
PD3_CTP_SDA: J16.26(CTP_SDA) R42.1
PD4_LCD_RD: J16.19(RD)
PD5_LCD_WR: J16.20(WR)
PD6_CTP_RST: J16.25(CTP_RST)
PD7_CTP_SCL: J16.24(CTP_SCL) R43.1
PD8_SMC_D13: J16.5(DB13)
PD9_SMC_D14: J16.4(DB14)
PD10_SMC_D15: J16.3(DB15)  [project net PD10_SDR_D10]
PD14_SMC_D0: J16.18(DB0)  [project net PD14_SDR_D13]
PD15_SMC_D1: J16.17(DB1)  [project net PD15_SDR_D14]
PE2_CTP_INT: J16.27(CTP_INT)
PE3_LCD_RST: J16.2(RESET)
PE7_SMC_D4: J16.14(DB4)
PE8_SMC_D5: J16.13(DB5)
PE9_SMC_D6: J16.12(DB6)
PE10_SMC_D7: J16.11(DB7)
PE11_SMC_D8: J16.10(DB8)
PE12_SMC_D9: J16.9(DB9)
PE13_SMC_D10: J16.8(DB10)
PE14_SMC_D11: J16.7(DB11)
PE15_SMC_D12: J16.6(DB12)
PF14_LCD_BK: J16.28(LCD_BL)
PG0_LCD_RS: J16.21(RS)
PG9: R44.1
PG10_LCD_CS: J16.22(LCD_CS)
NetD4_1: D4.1 R23.2
NetD5_1: D5.1 R24.2
NetD6_1: D6.1 R22.2
NetJ7_1: J7.1(DATA2) R55.1
NetJ7_2: J7.2(CM/DATA3) R48.1
NetJ7_3: J7.3(CMD) R57.1
NetJ7_5: J7.5(CLK) R56.1
NetJ7_7: J7.7(DATA0) R10.1
NetJ7_8: J7.8(DATA1) R19.1
NetJ16_23: J16.23(NC) R44.2
NetJ16_29: J16.29(5V) R46.2
NetJ16_30: J16.30(GND) R47.1

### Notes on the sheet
- Page6:TFCard&LED&LCD
- LED
- TF_CARD
- LCD
- ProjectName
- APM32F407 EVAL V1.1
- www.geehy.com
- DocumentName
- Page Number
- TFCard&LED&LCD
- 6/8

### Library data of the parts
C12 = CAP-2-NP-P: as C16 on sheet 01_Power Supply
D4-D6 = Diode-LED-2-N2-P: as D1 on sheet 01_Power Supply
R10 R19 R44 R46-R48 R55-R57 = RES-2-NP-P: as R9 on sheet 05_Memory&Camera&Button&BUZ
R22-R24 = 101RC-02070BW.01: as R30 on sheet 04_ETH
R42 R43 R50-R54 = RES-2-NP-P: as R59 on sheet 01_Power Supply

## Sheet 07_Communication.SchDoc
size A4; CompanyName: CYGRD; Organization: Altium Limited; Address1: L3, 12a Rodborough Rd; Address2: Frenchs Forest; Address3: NSW; Address4: Australia 2086
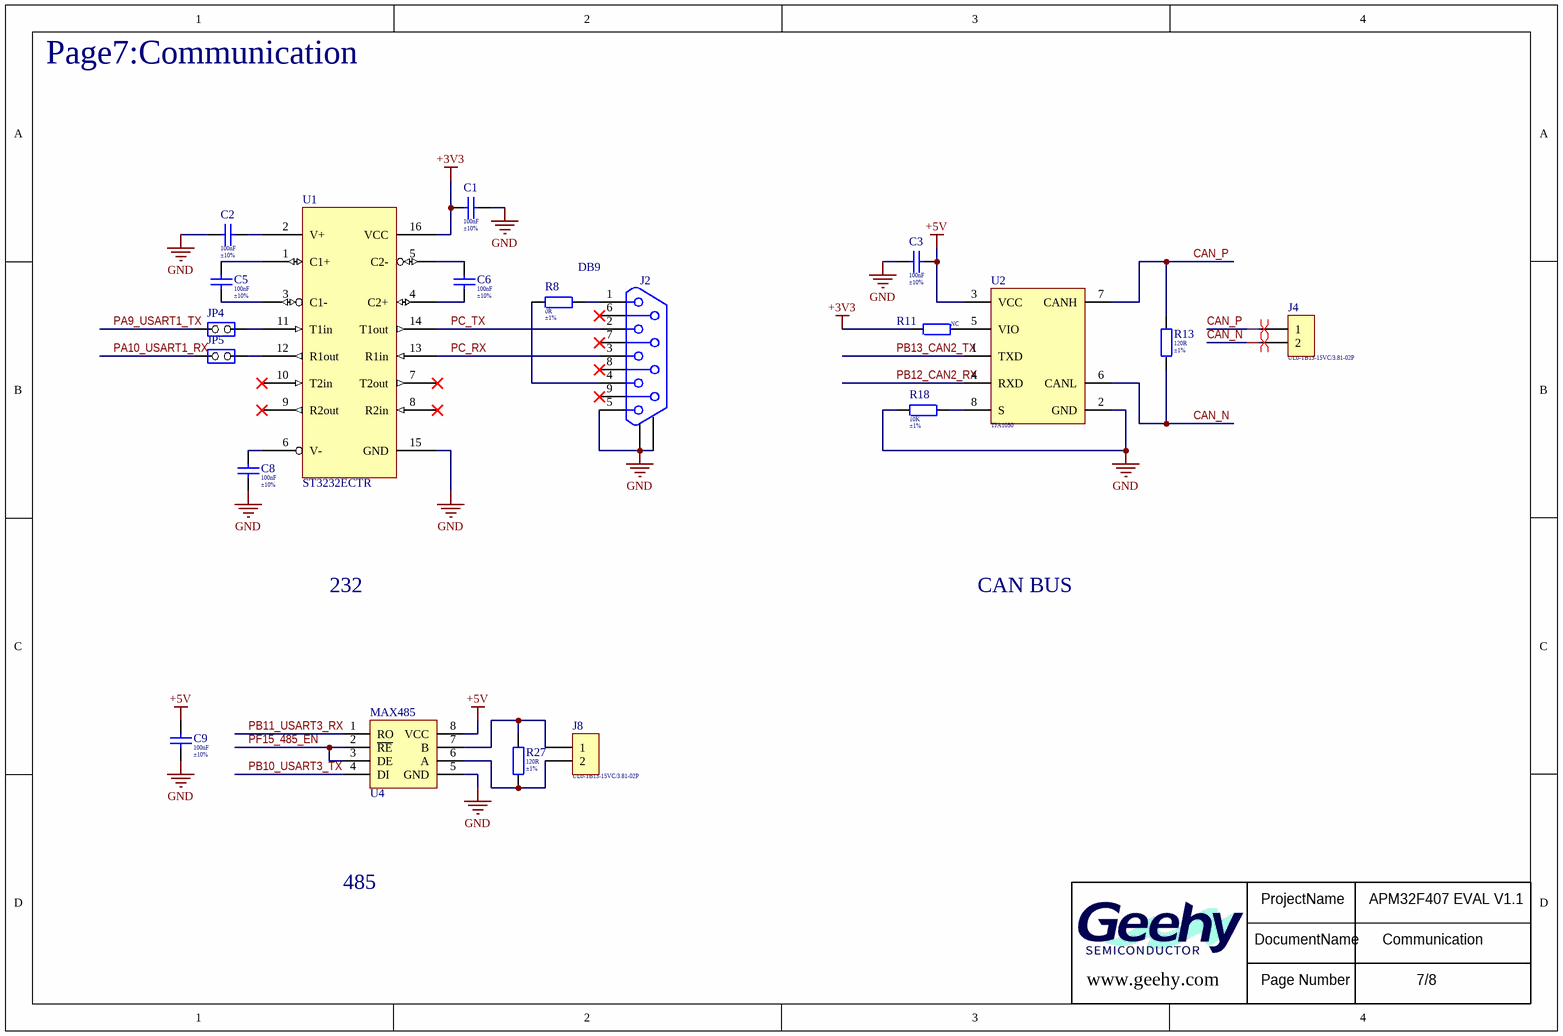
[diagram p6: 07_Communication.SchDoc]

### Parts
C1  Tolerance: ±10%  [C0603]  (hidden comment: 100nF)
C2  Tolerance: ±10%  [C0603]  (hidden comment: 100nF)
C3  Tolerance: ±10%  [C0603]  (hidden comment: 100nF)
C5  Tolerance: ±10%  [C0603]  (hidden comment: 100nF)
C6  Tolerance: ±10%  [C0603]  (hidden comment: 100nF)
C8  Tolerance: ±10%  [C0603]  (hidden comment: 100nF)
C9  Tolerance: ±10%  [C0603]  (hidden comment: 100nF)
J2  DB9  [DB9/F]
J4  UL0-TB13-15VC/3.81-02P  [2EDG2P-3R81-TH]
J8  UL0-TB13-15VC/3.81-02P  [2EDG2P-3R81-TH]
JP4  (no value)  [SIP2]
JP5  (no value)  [SIP2]
R8  Tolerance: ±1%  [R0603]  (hidden comment: 0R)
R11  NC  [R0603]
R13  Tolerance: ±1%  [R0603]  (hidden comment: 120R)
R18  Tolerance: ±1%  [R0603]  (hidden comment: 10K)
R27  Tolerance: ±1%  [R0603]  (hidden comment: 120R)
U1  ST3232ECTR  [TSSOP16]
U2  TJA1050  [SOIC8-1R27-5X4]
U4  MAX485  [SOIC8-1R27-5X4]

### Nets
+3V3: C1.2 R11.1 U1.16(VCC)
+5V: C3.2 C9.1 U2.3(VCC) U4.8(VCC)
GND: C1.1 C2.1 C3.1 C8.1 C9.2 J2.0 J2.5 R18.1 U1.15(GND) U2.2(GND) U4.5(GND)
CAN_N: J4.2 R13.2 U2.6(CANL)
CAN_P: J4.1 R13.1 U2.7(CANH)
PA9_USART1_TX: JP4.2(NO)
PA10_USART1_RX: JP5.2(NO)
PB10_USART3_TX: U4.4(DI)
PB11_USART3_RX: U4.1(RO)
PB12_CAN2_RX: U2.4(RXD)
PB13_CAN2_TX: U2.1(TXD)
PC_RX: J2.3 U1.13(R1in)
PC_TX: J2.2 U1.14(T1out)
PF15_485_EN: U4.2(~{RE}) U4.3(DE)
NetC2_2: C2.2 U1.2(V+)
NetC5_1: C5.1 U1.3(C1-)
NetC5_2: C5.2 U1.1(C1+)
NetC6_1: C6.1 U1.4(C2+)
NetC6_2: C6.2 U1.5(C2-)
NetC8_2: C8.2 U1.6(V-)
NetJ2_1: J2.1 R8.1
NetJ2_4: J2.4 R8.2
NetJ8_1: J8.1 R27.1 U4.7(B)
NetJ8_2: J8.2 R27.2 U4.6(A)
NetJP4_1: JP4.1(COMMON) U1.11(T1in)
NetJP5_1: JP5.1(COMMON) U1.12(R1out)
NetR11_2: R11.2 U2.5(VIO)
NetR18_2: R18.2 U2.8(S)

Not connected (* = marked no-connect by the designer): J2 6* 7* 8* 9*; U1 7(T2out)* 8(R2in)* 9(R2out)* 10(T2in)*

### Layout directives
differential pair: CAN_N, CAN_P

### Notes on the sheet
- Page7:Communication
- 232
- CAN BUS
- 485
- ProjectName
- APM32F407 EVAL V1.1
- www.geehy.com
- DocumentName
- Page Number
- Communication
- 7/8

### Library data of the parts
C1-C3 C5 C6 C8 C9 = CAP-2-NP-P: as C16 on sheet 01_Power Supply
J4 J8 = J-2-NP-P: 安装方式DIP,座子,封装脚距3.81mm,180度,2PIN,塑高/针长9.2/3.5mm,绿色,不带螺柱; Part Number: 102ND-00003FN.01; Allow Altenative Part: Y; serial number: 449; Categories: 连接器; COMPONENTLINK 1 DESCRIPTION: GetDatasheet; Modify time: 2018年9月29号; Preferred: P
JP4 JP5 = JP2
R8 = RES-2-NP-P: as R9 on sheet 05_Memory&Camera&Button&BUZ
R11 = RES-2-NP-P: SMD,阻值0R,精度±1%,0603,额定功率1/10W; Allow Altenative Part: Y; Tolerance: ±1%; Rated Power: 1/10W; serial number: 214; Categories: 电阻; COMPONENTLINK 1 DESCRIPTION: OpenDatasheet; Modify time: 2018年10月29号; Preferred: P
R13 R18 R27 = RES-2-NP-P: as R59 on sheet 01_Power Supply
U1 = ST3232: 3.3V/5V Dual RS232 Transceiver w/ Int. Cap.
U2 = 101IK-00037AY.01: 安装方式SMD,SO-8,8PIN,高速CAN收发器(工作电压为4.75~5.25V); Allow Altenative Part: Y; serial number: 1345; Categories: IC; COMPONENTLINK 1 DESCRIPTION: OpenDatasheet; Modify time: 2020年6月27号
U4 = 101IK-00033AR.01: 安装方式SMD,SOIC-8,8PIN,RS-485/RS-422收发器（工作电压4.75V~5.25V）; Allow Altenative Part: Y; Categories: IC; Value: MAX485CSA+; Modify time: 2019年2月16号; serial number: 952; COMPONENTLINK 1 DESCRIPTION: OpenDatasheet

## Sheet 08_USB&JTAG.SchDoc
size A4; CompanyName: CYGRD; Organization: Altium Limited; Address1: L3, 12a Rodborough Rd; Address2: Frenchs Forest; Address3: NSW; Address4: Australia 2086
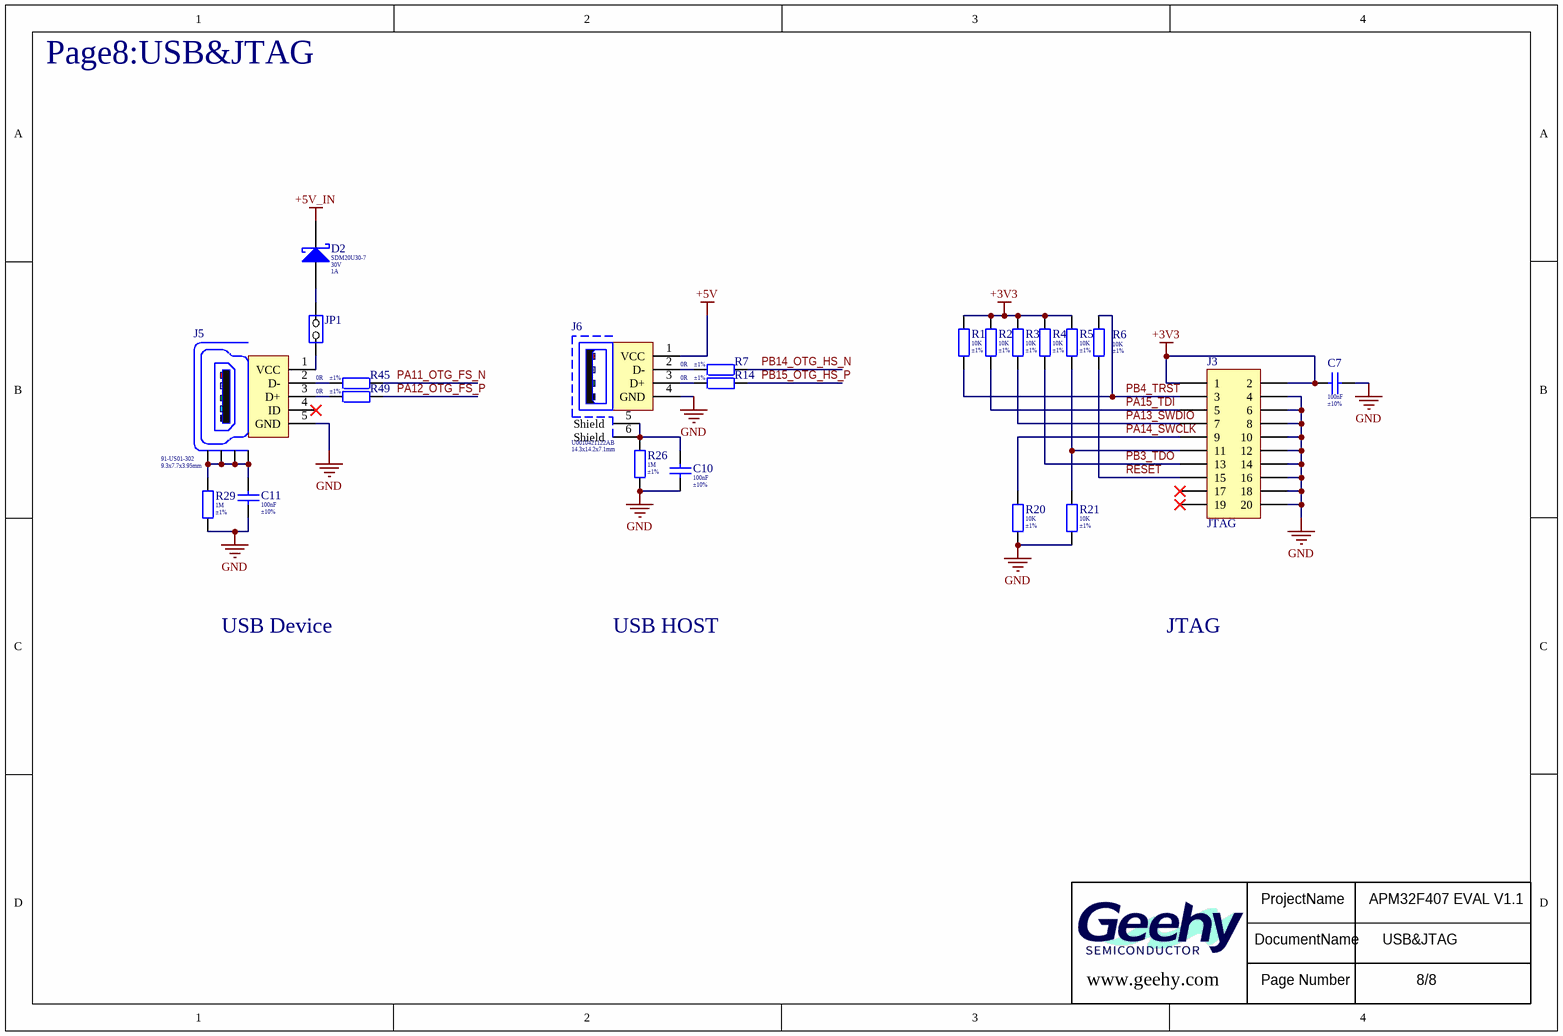
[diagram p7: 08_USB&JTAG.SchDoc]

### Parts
C7  Tolerance: ±10%  [C0603]  (hidden comment: 100nF)
C10  Tolerance: ±10%  [C0603]  (hidden comment: 100nF)
C11  Tolerance: ±10%  [C0603]  (hidden comment: 100nF)
D2  Rated Voltage: 30V  Rated Current: 1A  [SOD-523]  (hidden comment: SDM20U30-7)
J3  JTAG  [IDC20S]
J5  Size: 9.3x7.7x3.95mm  [USB-MiniB-SM-W]  (hidden comment: 91-US01-302)
J6  Size: 14.3x14.2x7.1mm  [USB-A-TH-W]  (hidden comment: U0010421122AB)
JP1  (no value)  [SIP2]
R1  Tolerance: ±1%  [R0603]  (hidden comment: 10K)
R2  Tolerance: ±1%  [R0603]  (hidden comment: 10K)
R3  Tolerance: ±1%  [R0603]  (hidden comment: 10K)
R4  Tolerance: ±1%  [R0603]  (hidden comment: 10K)
R5  Tolerance: ±1%  [R0603]  (hidden comment: 10K)
R6  Tolerance: ±1%  [R0603]  (hidden comment: 10K)
R7  Tolerance: ±1%  [R0603]  (hidden comment: 0R)
R14  Tolerance: ±1%  [R0603]  (hidden comment: 0R)
R20  Tolerance: ±1%  [R0603]  (hidden comment: 10K)
R21  Tolerance: ±1%  [R0603]  (hidden comment: 10K)
R26  Tolerance: ±1%  [R0603]  (hidden comment: 1M)
R29  Tolerance: ±1%  [R0603]  (hidden comment: 1M)
R45  Tolerance: ±1%  [R0603]  (hidden comment: 0R)
R49  Tolerance: ±1%  [R0603]  (hidden comment: 0R)

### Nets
+3V3: C7.1 J3.1 J3.2 R1.2 R2.2 R3.2 R4.2 R5.2
+5V: J6.1(VCC)
+5V_IN: D2.2
GND: C7.2 C10.2 C11.2 J3.4 J3.6 J3.8 J3.10 J3.12 J3.14 J3.16 J3.18 J3.20 J5.5(GND) J6.4(GND) R20.1 R21.1 R26.1 R29.1
PA11_OTG_FS_N: R45.1
PA12_OTG_FS_P: R49.1
PA13_SWDIO: J3.7 R3.1
PA14_SWCLK: J3.9 R20.2
PA15_TDI: J3.5 R2.1
PB3_TDO: J3.13 R4.1  [project net PB3_SPI_SCK]
PB4_TRST: J3.3 R1.1 R6.2  [project net PB4_SPI_MISO]
PB14_OTG_HS_N: R7.1
PB15_OTG_HS_P: R14.1
RESET: J3.15 R6.1
NetC10_1: C10.1 J6.5(Shield) J6.6(Shield) R26.2
NetC11_1: C11.1 J5.6(Shield) J5.7(Shield) J5.8(Shield) J5.9(Shield) R29.2
NetD2_1: D2.1 JP1.1(COMMON)
NetJ3_11: J3.11 R5.1 R21.2
NetJ5_1: J5.1(VCC) JP1.2(NO)
NetJ5_2: J5.2(D-) R45.2
NetJ5_3: J5.3(D+) R49.2
NetJ6_2: J6.2(D-) R7.2
NetJ6_3: J6.3(D+) R14.2

Not connected (* = marked no-connect by the designer): J3 17* 19*; J5 4(ID)*

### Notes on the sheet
- Page8:USB&JTAG
- USB Device
- USB HOST
- JTAG
- ProjectName
- APM32F407 EVAL V1.1
- www.geehy.com
- DocumentName
- Page Number
- USB&JTAG
- 8/8

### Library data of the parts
C7 C10 C11 = CAP-2-NP-P: as C16 on sheet 01_Power Supply
D2 = 101DS-00037AF.01: SMD,封装外壳SOD-523（0603）,额定电压30V,电流200mA; Allow Altenative Part: Y; serial number: 18; Categories: 二极管; COMPONENTLINK 1 DESCRIPTION: GetDatasheet; Modify time: 2015年11月11号; Approved: YES
J3 = Header 10X2: Header, 10-Pin, Dual row
J5 = Socket-MiniUSB-5-ID4-FP4-P: 安装方式SMD,MiniB口,封装尺寸9.3x7.7x3.95mm,触点材质：磷铜,颜色：黑色,90度,5PIN+4PIN(定位脚)+2PIN(定位脚),卧式; Part Number: 101OC-00001FP.01; Allow Altenative Part: Y; serial number: 262; Categories: 插座; COMPONENTLINK 1 DESCRIPTION: GetDatasheet; Modify time: 2020年6月13号; Preferred: P
J6 = Socket-USB-4-FP2-P: DIP,A口,封装尺寸14.3x14.2x7.1mm,触点材质/颜色铜镀镍/白色,90度,4+2PIN,卧式; Part Number: 102OC-00005CY.01; Allow Altenative Part: Y; serial number: 256; Categories: 插座; COMPONENTLINK 1 DESCRIPTION: GetDatasheet; Remark: Verified by BU4（陈雪莹） check list V1.0; Modify time: 2017年01月07号; Approved: YES; Preferred: P
JP1 = JP2
R1-R6 R20 R21 R26 R29 = RES-2-NP-P: as R59 on sheet 01_Power Supply
R7 R14 R45 R49 = RES-2-NP-P: as R9 on sheet 05_Memory&Camera&Button&BUZ

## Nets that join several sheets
+3V3: 01_Power Supply (5 pins), 02_MCU_Connect (J12.1 J12.2 J13.79 J13.80), 03_GPIO (7 pins), 04_ETH (C28.1 L1.1 U6.9), 05_Memory&Camera&Button&BUZ (7 pins), 06_TFCard&LED&LCD (13 pins), 07_Communication (C1.2 R11.1 U1.16), 08_USB&JTAG (8 pins)
+5V: 01_Power Supply (6 pins), 02_MCU_Connect (J12.3 J12.4), 03_GPIO (J14.3 J14.4), 05_Memory&Camera&Button&BUZ (J1.1), 06_TFCard&LED&LCD (R46.1), 07_Communication (C3.2 C9.1 U2.3 U4.8), 08_USB&JTAG (J6.1)
+5V_IN: 01_Power Supply (J9.2 L2.1), 08_USB&JTAG (D2.2)
GND: 01_Power Supply (10 pins), 02_MCU_Connect (15 pins), 03_GPIO (18 pins), 04_ETH (24 pins), 05_Memory&Camera&Button&BUZ (16 pins), 06_TFCard&LED&LCD (9 pins), 07_Communication (11 pins), 08_USB&JTAG (18 pins)
BOOT0: 02_MCU_Connect (J12.52), 03_GPIO (J14.52 R61.2)
PA0_CAMRE_PW: 02_MCU_Connect (J13.68), 03_GPIO (J15.68), 05_Memory&Camera&Button&BUZ (J1.3)
PA1_RMII_REF_CLK: 02_MCU_Connect (J13.67), 03_GPIO (J15.67), 04_ETH (U6.14)
PA2_ETH_MDIO: 02_MCU_Connect (J13.66), 03_GPIO (J15.66), 04_ETH (R30.2)
PA3_SDR_CKE: 02_MCU_Connect (J13.58), 03_GPIO (J15.58)
PA4_DCMI_HS: 02_MCU_Connect (J13.57), 03_GPIO (J15.57), 05_Memory&Camera&Button&BUZ (J1.17)
PA5_KEY4: 02_MCU_Connect (J13.56), 03_GPIO (J15.56), 05_Memory&Camera&Button&BUZ (S4.3 S4.4)
PA6_DCMI_PIXCK: 02_MCU_Connect (J13.55), 03_GPIO (J15.55), 05_Memory&Camera&Button&BUZ (J1.9)
PA7_RMII_CRS_DV: 02_MCU_Connect (J13.54), 03_GPIO (J15.54), 04_ETH (U6.11)
PA8_CAMER_XCLK: 02_MCU_Connect (J12.12), 03_GPIO (J14.12), 05_Memory&Camera&Button&BUZ (J1.7)
PA9_USART1_TX: 02_MCU_Connect (J12.13), 03_GPIO (J14.13), 07_Communication (JP4.2)
PA10_USART1_RX: 02_MCU_Connect (J12.15), 03_GPIO (J14.15), 07_Communication (JP5.2)
PA11_OTG_FS_N: 02_MCU_Connect (J12.14), 03_GPIO (J14.14), 08_USB&JTAG (R45.1)
PA12_OTG_FS_P: 02_MCU_Connect (J12.16), 03_GPIO (J14.16), 08_USB&JTAG (R49.1)
PA13_SWDIO: 02_MCU_Connect (J12.17), 03_GPIO (J14.17), 08_USB&JTAG (J3.7 R3.1)
PA14_SWCLK: 02_MCU_Connect (J12.27), 03_GPIO (J14.27), 08_USB&JTAG (J3.9 R20.2)
PA15_TDI: 02_MCU_Connect (J12.28), 03_GPIO (J14.28), 08_USB&JTAG (J3.5 R2.1)
PB0_KEY1: 02_MCU_Connect (J13.51), 03_GPIO (J15.51), 05_Memory&Camera&Button&BUZ (S1.3 S1.4)
PB1_KEY2: 02_MCU_Connect (J13.50), 03_GPIO (J15.50), 05_Memory&Camera&Button&BUZ (S2.3 S2.4)
PB2_BOOT1: 02_MCU_Connect (J13.49), 03_GPIO (J15.49 R62.2)
PB3_SPI_SCK: 02_MCU_Connect (J12.47), 03_GPIO (J14.47), 05_Memory&Camera&Button&BUZ (R17.2), 08_USB&JTAG (J3.13 R4.1)
PB4_SPI_MISO: 02_MCU_Connect (J12.48), 03_GPIO (J14.48), 05_Memory&Camera&Button&BUZ (R15.1), 08_USB&JTAG (J3.3 R1.1 R6.2)
PB5_SPI_MOSI: 02_MCU_Connect (J12.49), 03_GPIO (J14.49), 05_Memory&Camera&Button&BUZ (R12.2)
PB6_DCMI_D5: 02_MCU_Connect (J12.50), 03_GPIO (J14.50), 05_Memory&Camera&Button&BUZ (J1.12)
PB7_DCMI_VS: 02_MCU_Connect (J12.51), 03_GPIO (J14.51), 05_Memory&Camera&Button&BUZ (J1.11)
PB8_I2C1_SCL: 02_MCU_Connect (J12.53), 03_GPIO (J14.53), 05_Memory&Camera&Button&BUZ (J1.18)
PB9_I2C1_SDA: 02_MCU_Connect (J12.54), 03_GPIO (J14.54), 05_Memory&Camera&Button&BUZ (J1.20)
PB10_USART3_TX: 02_MCU_Connect (J13.32), 03_GPIO (J15.32), 07_Communication (U4.4)
PB11_USART3_RX: 02_MCU_Connect (J13.31), 03_GPIO (J15.31), 07_Communication (U4.1)
PB12_CAN2_RX: 02_MCU_Connect (J13.20), 03_GPIO (J15.20), 07_Communication (U2.4)
PB13_CAN2_TX: 02_MCU_Connect (J13.18), 03_GPIO (J15.18), 07_Communication (U2.1)
PB14_OTG_HS_N: 02_MCU_Connect (J13.21), 03_GPIO (J15.21), 08_USB&JTAG (R7.1)
PB15_OTG_HS_P: 02_MCU_Connect (J13.19), 03_GPIO (J15.19), 08_USB&JTAG (R14.1)
PC0_LED1: 02_MCU_Connect (J13.72), 03_GPIO (J15.72), 06_TFCard&LED&LCD (D6.2)
PC1_ETH_MDC: 02_MCU_Connect (J13.71), 03_GPIO (J15.71), 04_ETH (U6.13)
PC2_LED2: 02_MCU_Connect (J13.70), 03_GPIO (J15.70), 06_TFCard&LED&LCD (D4.2)
PC3_LED3: 02_MCU_Connect (J13.69), 03_GPIO (J15.69), 06_TFCard&LED&LCD (D5.2)
PC4_RMII_RXD0: 02_MCU_Connect (J13.53), 03_GPIO (J15.53), 04_ETH (U6.8)
PC5_RMII_RXD1: 02_MCU_Connect (J13.52), 03_GPIO (J15.52), 04_ETH (U6.7)
PC6_DCMI_D0: 02_MCU_Connect (J12.8), 03_GPIO (J14.8), 05_Memory&Camera&Button&BUZ (J1.2)
PC7_DCMI_D1: 02_MCU_Connect (J12.9), 03_GPIO (J14.9), 05_Memory&Camera&Button&BUZ (J1.4)
PC8_SDIO_D0: 02_MCU_Connect (J12.10), 03_GPIO (J14.10), 05_Memory&Camera&Button&BUZ (J1.6), 06_TFCard&LED&LCD (R10.2 R54.1)
PC9_SDIO_D1: 02_MCU_Connect (J12.11), 03_GPIO (J14.11), 05_Memory&Camera&Button&BUZ (J1.8), 06_TFCard&LED&LCD (R19.2 R53.1)
PC10_SDIO_D2: 02_MCU_Connect (J12.29), 03_GPIO (J14.29), 06_TFCard&LED&LCD (R52.1 R55.2)
PC11_SDIO_D3: 02_MCU_Connect (J12.30), 03_GPIO (J14.30), 06_TFCard&LED&LCD (R48.2 R51.1)
PC12_SDIO_CLK: 02_MCU_Connect (J12.31), 03_GPIO (J14.31), 06_TFCard&LED&LCD (R56.2)
PC13: 02_MCU_Connect (J12.70), 03_GPIO (J14.70)
PD0_SMC_D2: 02_MCU_Connect (J12.32), 03_GPIO (J14.32), 06_TFCard&LED&LCD (J16.16)
PD1_SMC_D3: 02_MCU_Connect (J12.33), 03_GPIO (J14.33), 06_TFCard&LED&LCD (J16.15)
PD2_SDIO_CMD: 02_MCU_Connect (J12.34), 03_GPIO (J14.34), 06_TFCard&LED&LCD (R50.1 R57.2)
PD3_CTP_SDA: 02_MCU_Connect (J12.35), 03_GPIO (J14.35), 06_TFCard&LED&LCD (J16.26 R42.1)
PD4_LCD_RD: 02_MCU_Connect (J12.36), 03_GPIO (J14.36), 06_TFCard&LED&LCD (J16.19)
PD5_LCD_WR: 02_MCU_Connect (J12.37), 03_GPIO (J14.37), 06_TFCard&LED&LCD (J16.20)
PD6_CTP_RST: 02_MCU_Connect (J12.38), 03_GPIO (J14.38), 06_TFCard&LED&LCD (J16.25)
PD7_CTP_SCL: 02_MCU_Connect (J12.39), 03_GPIO (J14.39), 06_TFCard&LED&LCD (J16.24 R43.1)
PD8_SMC_D13: 02_MCU_Connect (J13.17), 03_GPIO (J15.17), 06_TFCard&LED&LCD (J16.5)
PD9_SMC_D14: 02_MCU_Connect (J13.16), 03_GPIO (J15.16), 06_TFCard&LED&LCD (J16.4)
PD10_SDR_D10: 02_MCU_Connect (J13.15), 03_GPIO (J15.15), 06_TFCard&LED&LCD (J16.3)
PD11_ETH_RESET: 02_MCU_Connect (J13.14), 03_GPIO (J15.14), 04_ETH (R39.2 U6.15)
PD12_SDR_D11: 02_MCU_Connect (J13.13), 03_GPIO (J15.13)
PD13_SDR_D12: 02_MCU_Connect (J13.12), 03_GPIO (J15.12)
PD14_SDR_D13: 02_MCU_Connect (J13.11), 03_GPIO (J15.11), 06_TFCard&LED&LCD (J16.18)
PD15_SDR_D14: 02_MCU_Connect (J13.10), 03_GPIO (J15.10), 06_TFCard&LED&LCD (J16.17)
PE0: 02_MCU_Connect (J12.55), 03_GPIO (J14.55)
PE1: 02_MCU_Connect (J12.56), 03_GPIO (J14.56)
PE2_CTP_INT: 02_MCU_Connect (J12.63), 03_GPIO (J14.63), 06_TFCard&LED&LCD (J16.27)
PE3_LCD_RST: 02_MCU_Connect (J12.64), 03_GPIO (J14.64), 06_TFCard&LED&LCD (J16.2)
PE4_DCMI_D4: 02_MCU_Connect (J12.65), 03_GPIO (J14.65), 05_Memory&Camera&Button&BUZ (J1.10)
PE5_DCMI_D6: 02_MCU_Connect (J12.66), 03_GPIO (J14.66), 05_Memory&Camera&Button&BUZ (J1.14)
PE6_DCMI_D7: 02_MCU_Connect (J12.67), 03_GPIO (J14.67), 05_Memory&Camera&Button&BUZ (J1.16)
PE7_SMC_D4: 02_MCU_Connect (J13.41), 03_GPIO (J15.41), 06_TFCard&LED&LCD (J16.14)
PE8_SMC_D5: 02_MCU_Connect (J13.40), 03_GPIO (J15.40), 06_TFCard&LED&LCD (J16.13)
PE9_SMC_D6: 02_MCU_Connect (J13.39), 03_GPIO (J15.39), 06_TFCard&LED&LCD (J16.12)
PE10_SMC_D7: 02_MCU_Connect (J13.38), 03_GPIO (J15.38), 06_TFCard&LED&LCD (J16.11)
PE11_SMC_D8: 02_MCU_Connect (J13.37), 03_GPIO (J15.37), 06_TFCard&LED&LCD (J16.10)
PE12_SMC_D9: 02_MCU_Connect (J13.36), 03_GPIO (J15.36), 06_TFCard&LED&LCD (J16.9)
PE13_SMC_D10: 02_MCU_Connect (J13.35), 03_GPIO (J15.35), 06_TFCard&LED&LCD (J16.8)
PE14_SMC_D11: 02_MCU_Connect (J13.34), 03_GPIO (J15.34), 06_TFCard&LED&LCD (J16.7)
PE15_SMC_D12: 02_MCU_Connect (J13.33), 03_GPIO (J15.33), 06_TFCard&LED&LCD (J16.6)
PF0_SDR_A10: 02_MCU_Connect (J12.74), 03_GPIO (J14.74)
PF1_SDR_A0: 02_MCU_Connect (J12.75), 03_GPIO (J14.75)
PF2_SDR_A1: 02_MCU_Connect (J12.76), 03_GPIO (J14.76)
PF3_SDR_A2: 02_MCU_Connect (J12.77), 03_GPIO (J14.77)
PF4_SDR_A3: 02_MCU_Connect (J12.78), 03_GPIO (J14.78)
PF5_SPI_CS: 02_MCU_Connect (J12.79), 03_GPIO (J14.79), 05_Memory&Camera&Button&BUZ (R16.2)
PF6_SDR_A4: 02_MCU_Connect (J13.78), 03_GPIO (J15.78)
PF7_SDR_A5: 02_MCU_Connect (J13.77), 03_GPIO (J15.77)
PF8_SDR_A6: 02_MCU_Connect (J13.76), 03_GPIO (J15.76)
PF9_SDR_A7: 02_MCU_Connect (J13.75), 03_GPIO (J15.75)
PF10_SDR_A8: 02_MCU_Connect (J13.74), 03_GPIO (J15.74)
PF11_SDR_UDQM: 02_MCU_Connect (J13.48), 03_GPIO (J15.48)
PF12_KEY3: 02_MCU_Connect (J13.47), 03_GPIO (J15.47), 05_Memory&Camera&Button&BUZ (S3.3 S3.4)
PF13_CAMER_RST: 02_MCU_Connect (J13.46), 03_GPIO (J15.46), 05_Memory&Camera&Button&BUZ (J1.5)
PF14_LCD_BK: 02_MCU_Connect (J13.45), 03_GPIO (J15.45), 06_TFCard&LED&LCD (J16.28)
PF15_485_EN: 02_MCU_Connect (J13.44), 03_GPIO (J15.44), 07_Communication (U4.2 U4.3)
PG0_LCD_RS: 02_MCU_Connect (J13.43), 03_GPIO (J15.43), 06_TFCard&LED&LCD (J16.21)
PG1_SDR_CLK: 02_MCU_Connect (J13.42), 03_GPIO (J15.42)
PG2_SDR_D15: 02_MCU_Connect (J13.9), 03_GPIO (J15.9)
PG3_SDR_D0: 02_MCU_Connect (J13.8), 03_GPIO (J15.8)
PG4_SDR_D1: 02_MCU_Connect (J13.7), 03_GPIO (J15.7)
PG5_SDR_D2: 02_MCU_Connect (J13.6), 03_GPIO (J15.6)
PG6_SDR_D3: 02_MCU_Connect (J13.5), 03_GPIO (J15.5)
PG7_BUZ: 02_MCU_Connect (J13.3), 03_GPIO (J15.3), 05_Memory&Camera&Button&BUZ (R25.2)
PG8_SDR_D4: 02_MCU_Connect (J12.7), 03_GPIO (J14.7)
PG9: 02_MCU_Connect (J12.40), 03_GPIO (J14.40), 06_TFCard&LED&LCD (R44.1)
PG10_LCD_CS: 02_MCU_Connect (J12.41), 03_GPIO (J14.41), 06_TFCard&LED&LCD (J16.22)
PG11_RMII_TX_EN: 02_MCU_Connect (J12.42), 03_GPIO (J14.42), 04_ETH (U6.16)
PG12: 02_MCU_Connect (J12.43), 03_GPIO (J14.43)
PG13_RMII_TXD0: 02_MCU_Connect (J12.44), 03_GPIO (J14.44), 04_ETH (U6.17)
PG14_RMII_TXD1: 02_MCU_Connect (J12.45), 03_GPIO (J14.45), 04_ETH (U6.18)
PG15_SDR_LDQM: 02_MCU_Connect (J12.46), 03_GPIO (J14.46)
PH2: 02_MCU_Connect (J13.65), 03_GPIO (J15.65)
PH3_SDR_A9: 02_MCU_Connect (J13.64), 03_GPIO (J15.64)
PH4: 02_MCU_Connect (J13.60), 03_GPIO (J15.60)
PH5_SDR_CKE: 02_MCU_Connect (J13.59), 03_GPIO (J15.59)
PH6: 02_MCU_Connect (J13.30), 03_GPIO (J15.30)
PH7: 02_MCU_Connect (J13.29), 03_GPIO (J15.29)
PH8_SDR_D8: 02_MCU_Connect (J13.28), 03_GPIO (J15.28)
PH9: 02_MCU_Connect (J13.27), 03_GPIO (J15.27)
PH10_SDR_D9: 02_MCU_Connect (J13.26), 03_GPIO (J15.26)
PH11: 02_MCU_Connect (J13.25), 03_GPIO (J15.25)
PH12: 02_MCU_Connect (J13.22), 03_GPIO (J15.22)
PH13_SDR_D5: 02_MCU_Connect (J12.18), 03_GPIO (J14.18)
PH14: 02_MCU_Connect (J12.19), 03_GPIO (J14.19)
PH15_SDR_D6: 02_MCU_Connect (J12.20), 03_GPIO (J14.20)
PI0: 02_MCU_Connect (J12.21), 03_GPIO (J14.21)
PI1: 02_MCU_Connect (J12.22), 03_GPIO (J14.22)
PI2: 02_MCU_Connect (J12.25), 03_GPIO (J14.25)
PI3_SDR_D7: 02_MCU_Connect (J12.26), 03_GPIO (J14.26)
PI4: 02_MCU_Connect (J12.57), 03_GPIO (J14.57)
PI5: 02_MCU_Connect (J12.58), 03_GPIO (J14.58)
PI6: 02_MCU_Connect (J12.59), 03_GPIO (J14.59)
PI7_SDR_NWE: 02_MCU_Connect (J12.60), 03_GPIO (J14.60)
PI8_SDR_NCAS: 02_MCU_Connect (J12.69), 03_GPIO (J14.69)
PI9_SDR_NRAS: 02_MCU_Connect (J12.71), 03_GPIO (J14.71)
PI10_SDR_NCS: 02_MCU_Connect (J12.72), 03_GPIO (J14.72)
PI11_SDR_BA: 02_MCU_Connect (J12.73), 03_GPIO (J14.73)
RESET: 02_MCU_Connect (J13.73), 03_GPIO (J15.73), 05_Memory&Camera&Button&BUZ (C33.2 R58.2 S5.3 S5.4), 08_USB&JTAG (J3.15 R6.1)
VBAT_IN: 02_MCU_Connect (J12.68), 03_GPIO (D7.3 J14.68)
